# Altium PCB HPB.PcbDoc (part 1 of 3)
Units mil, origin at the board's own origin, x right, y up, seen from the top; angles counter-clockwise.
Board outline 7000 x 12000 mil, 6 copper layers (Top Layer, Int1 (GND), Int2 (Sign), Int3 (Sign), Int4 (PWR), Bottom Layer), stack 61.068 mil thick; 321 components, 232 nets, 1034 pads, 269 vias.
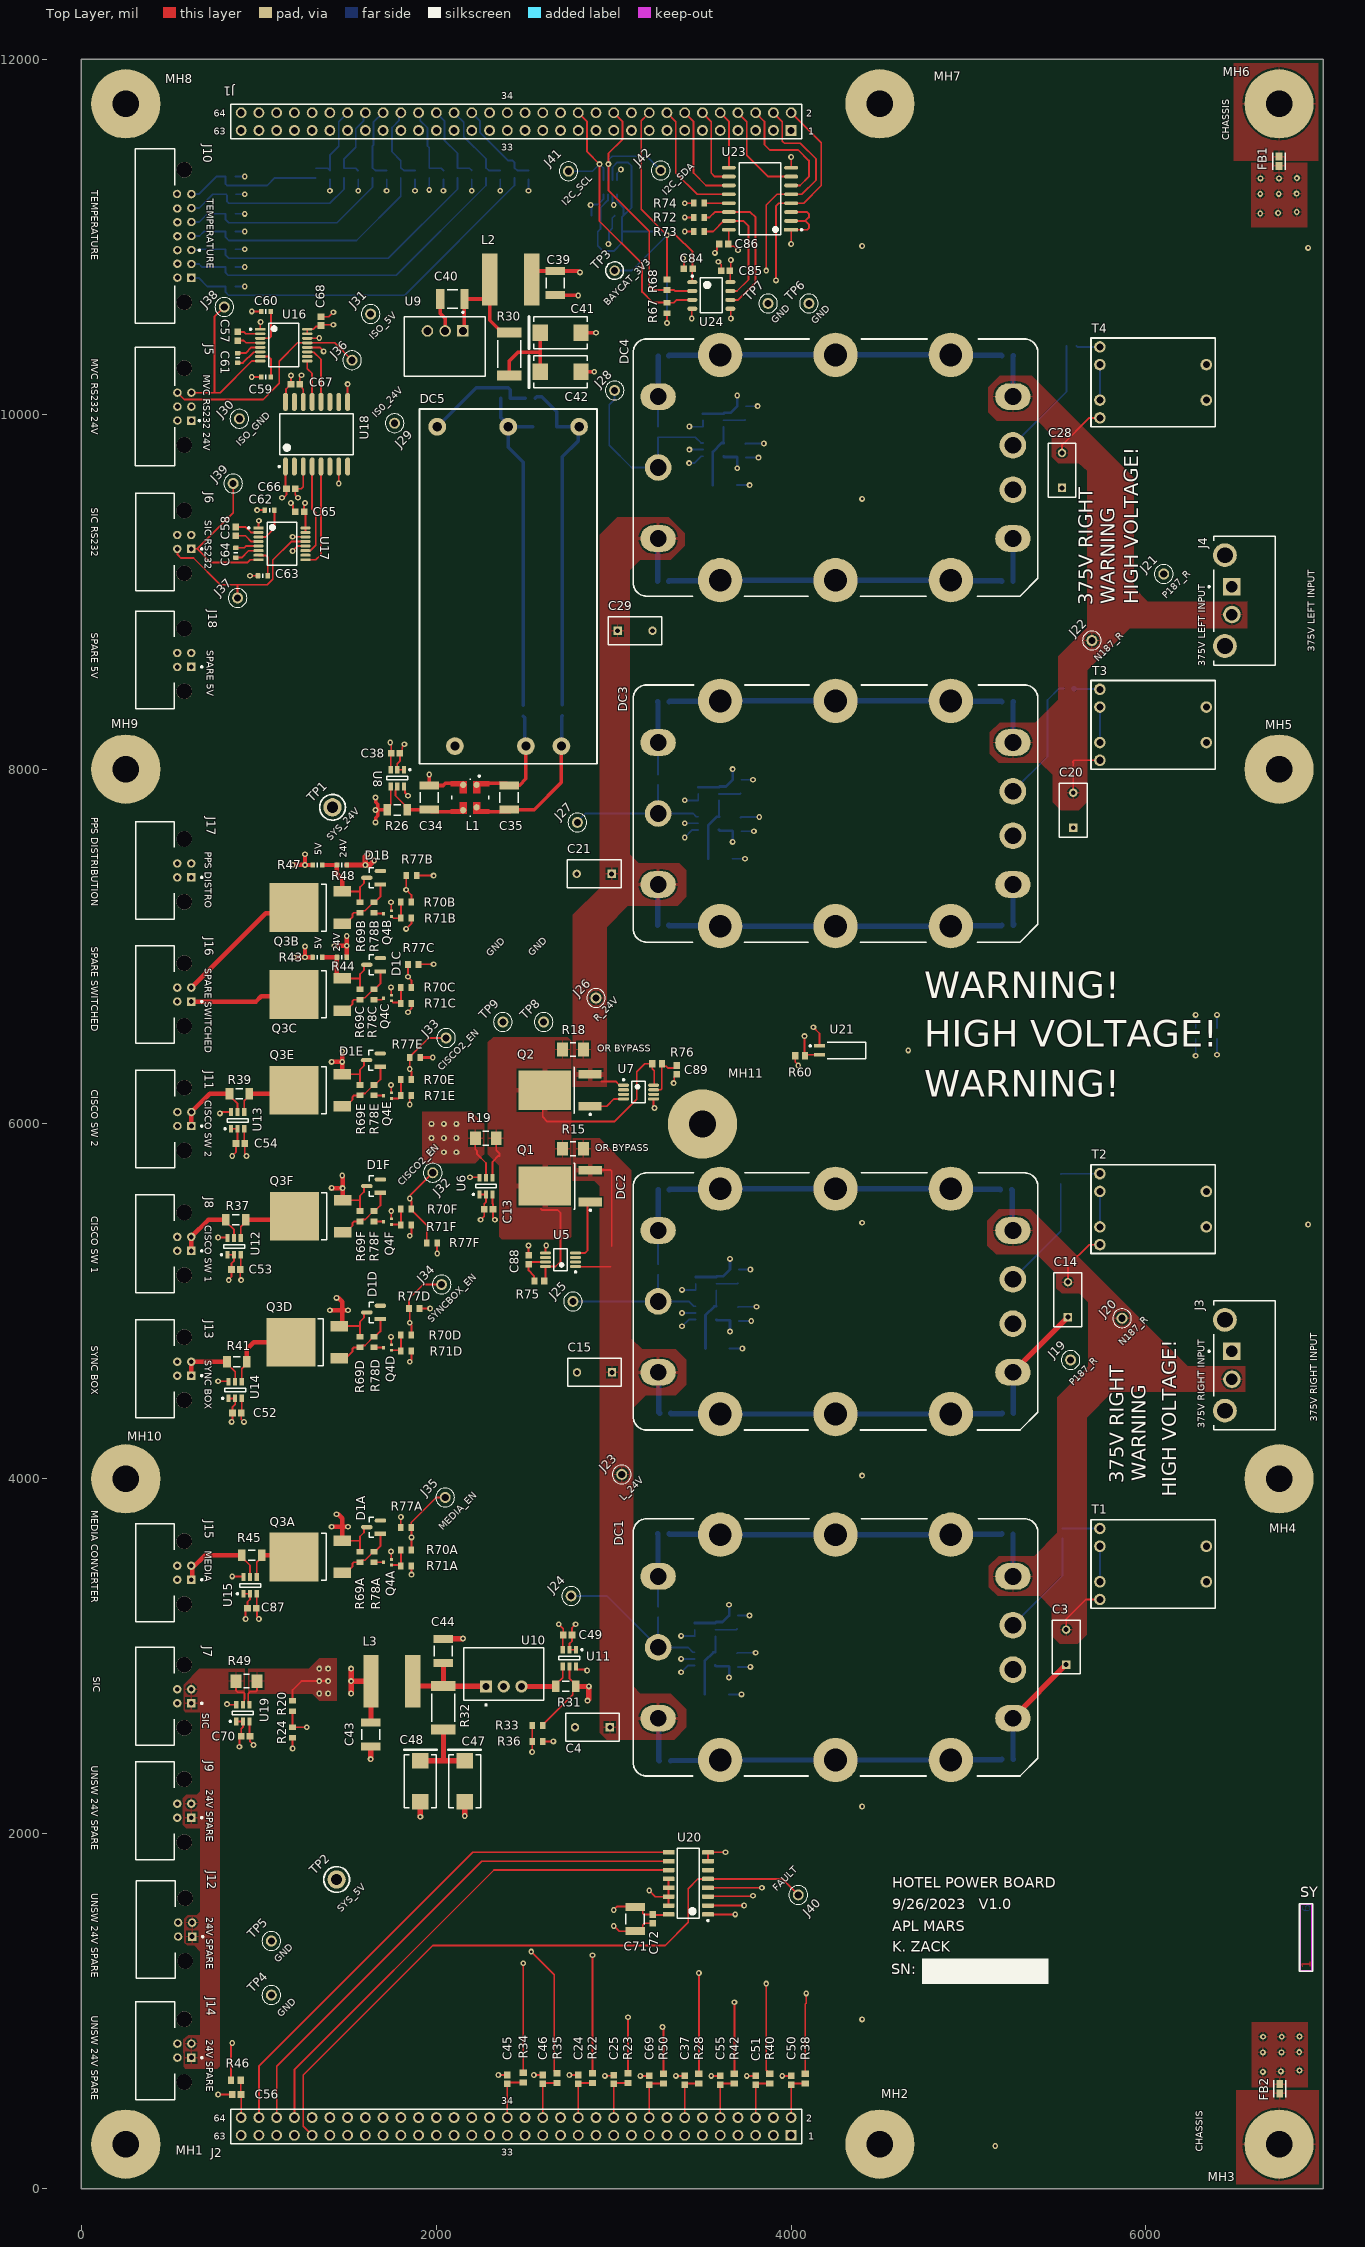
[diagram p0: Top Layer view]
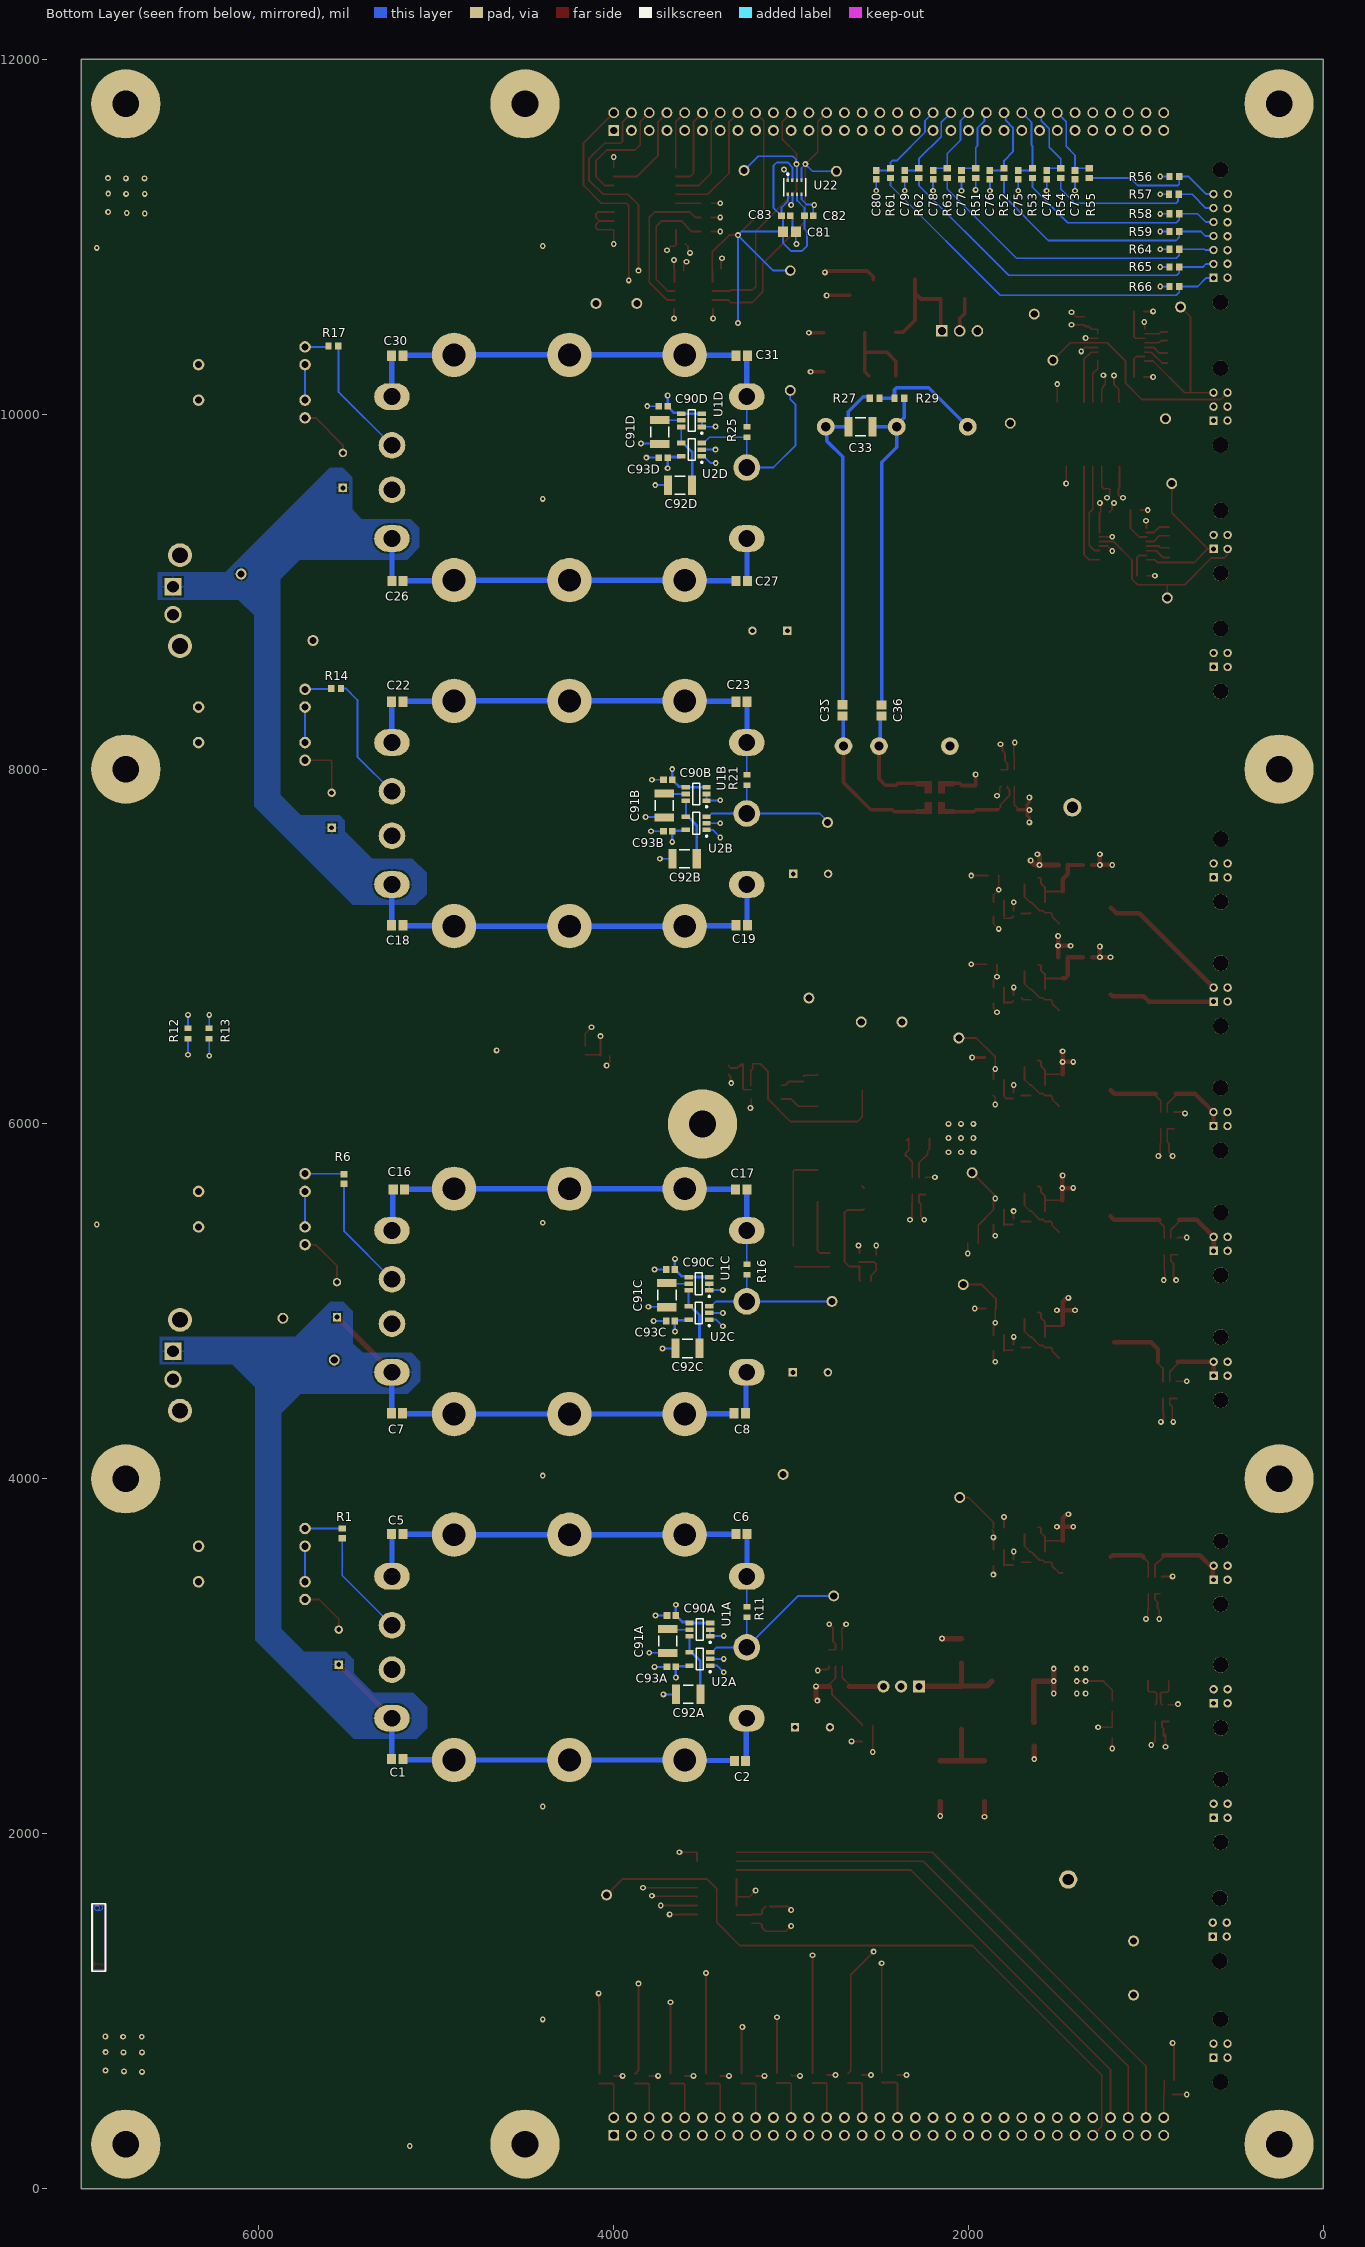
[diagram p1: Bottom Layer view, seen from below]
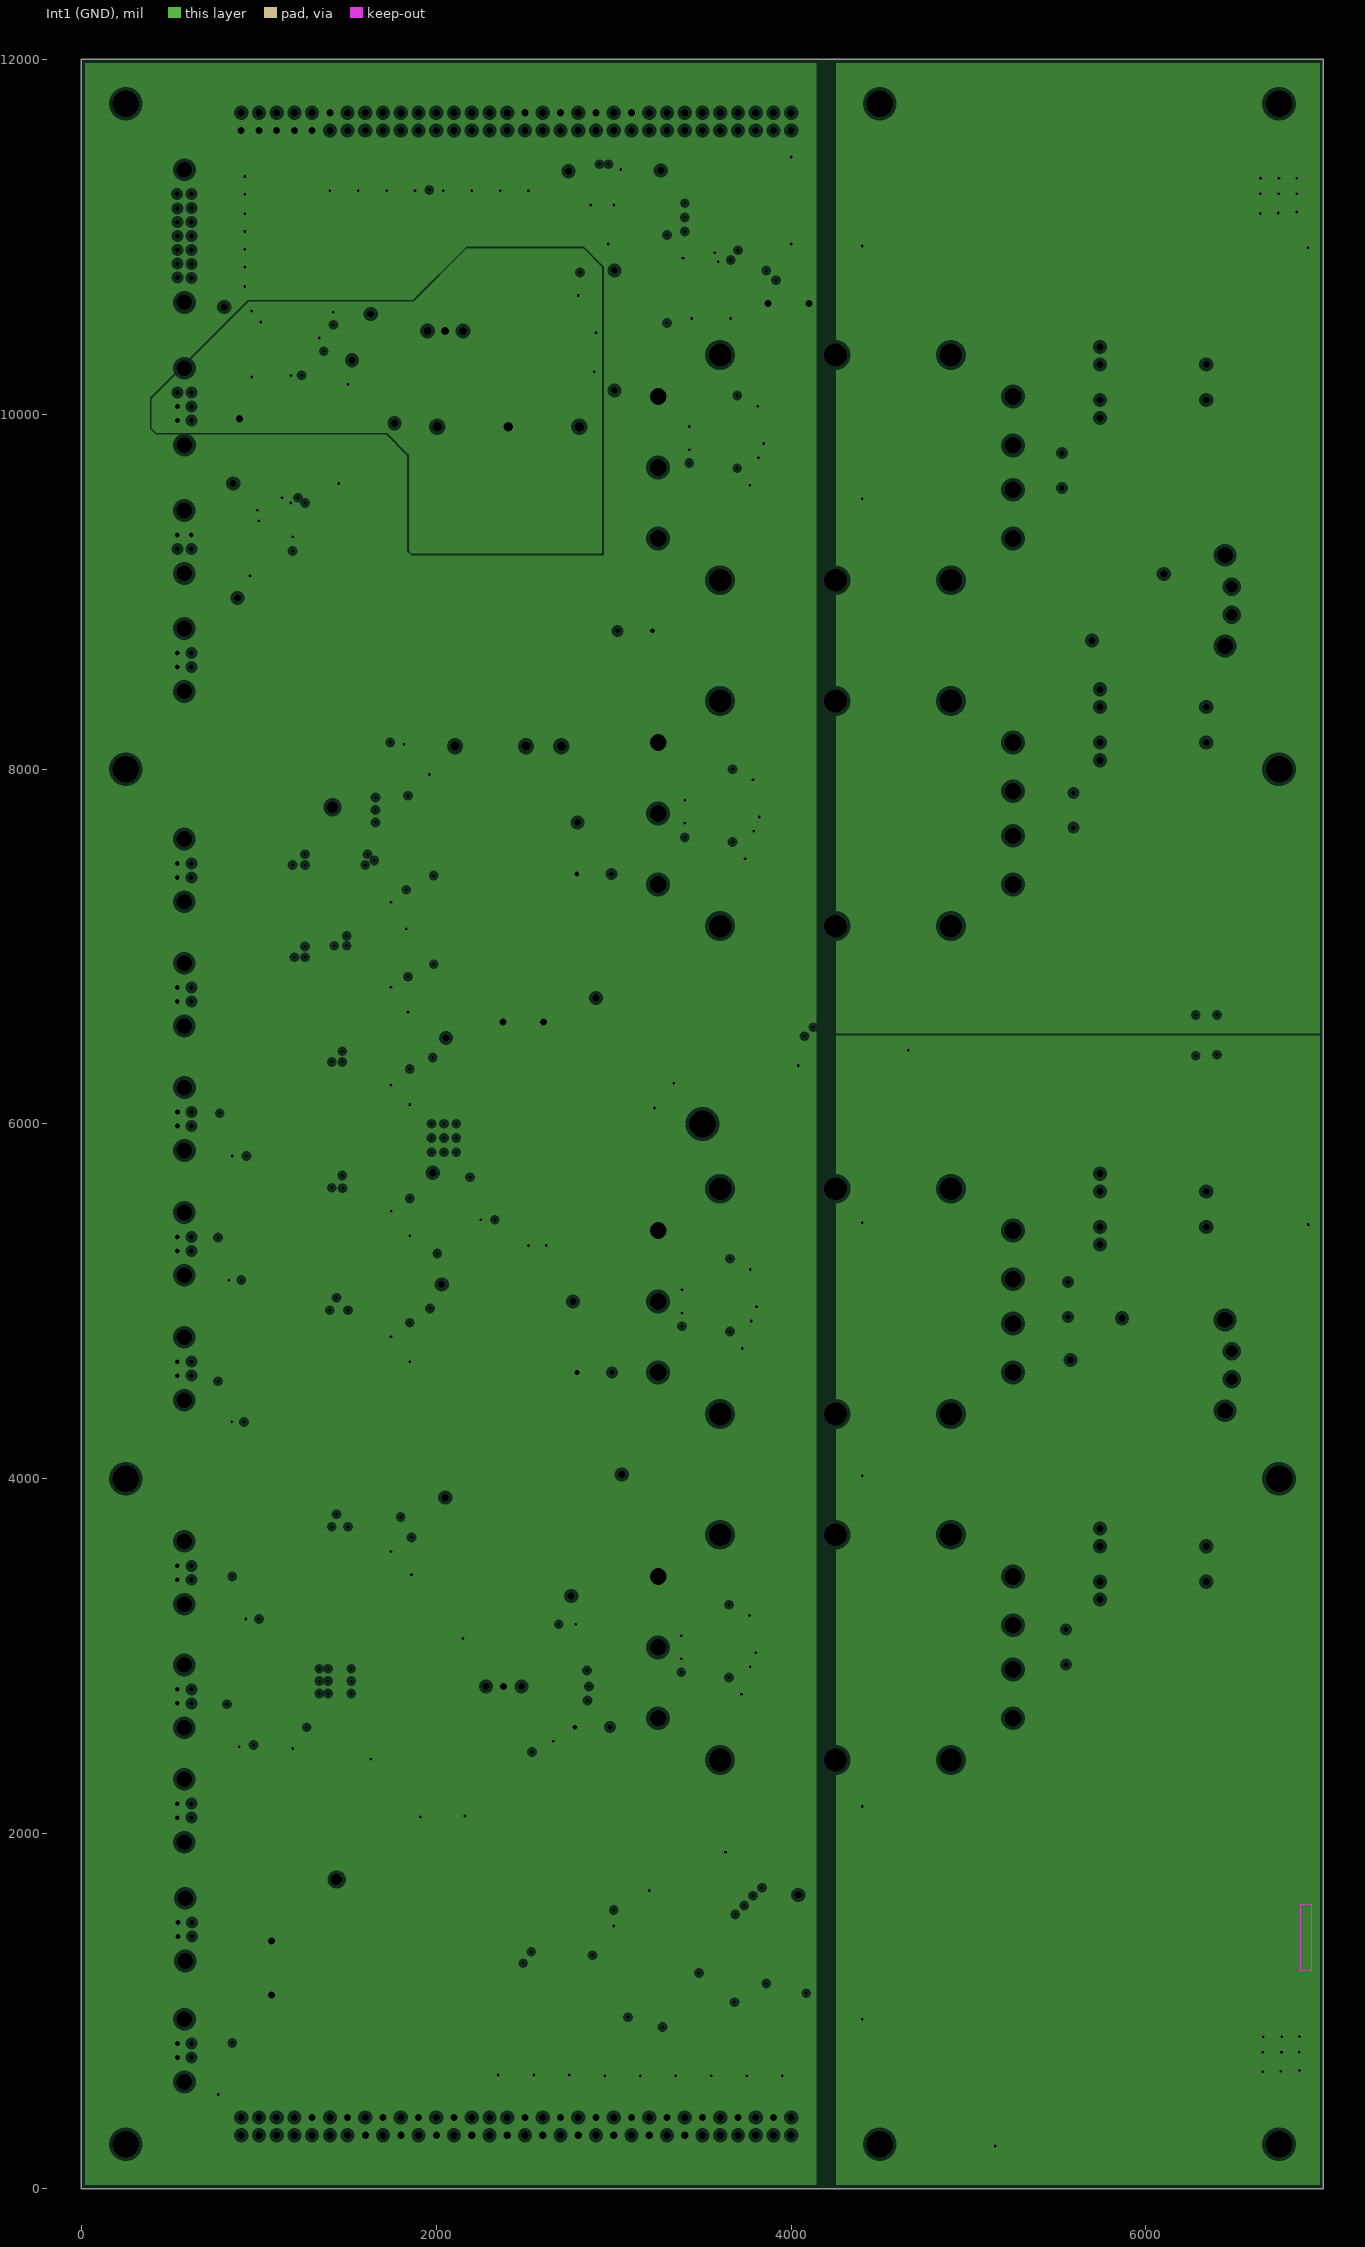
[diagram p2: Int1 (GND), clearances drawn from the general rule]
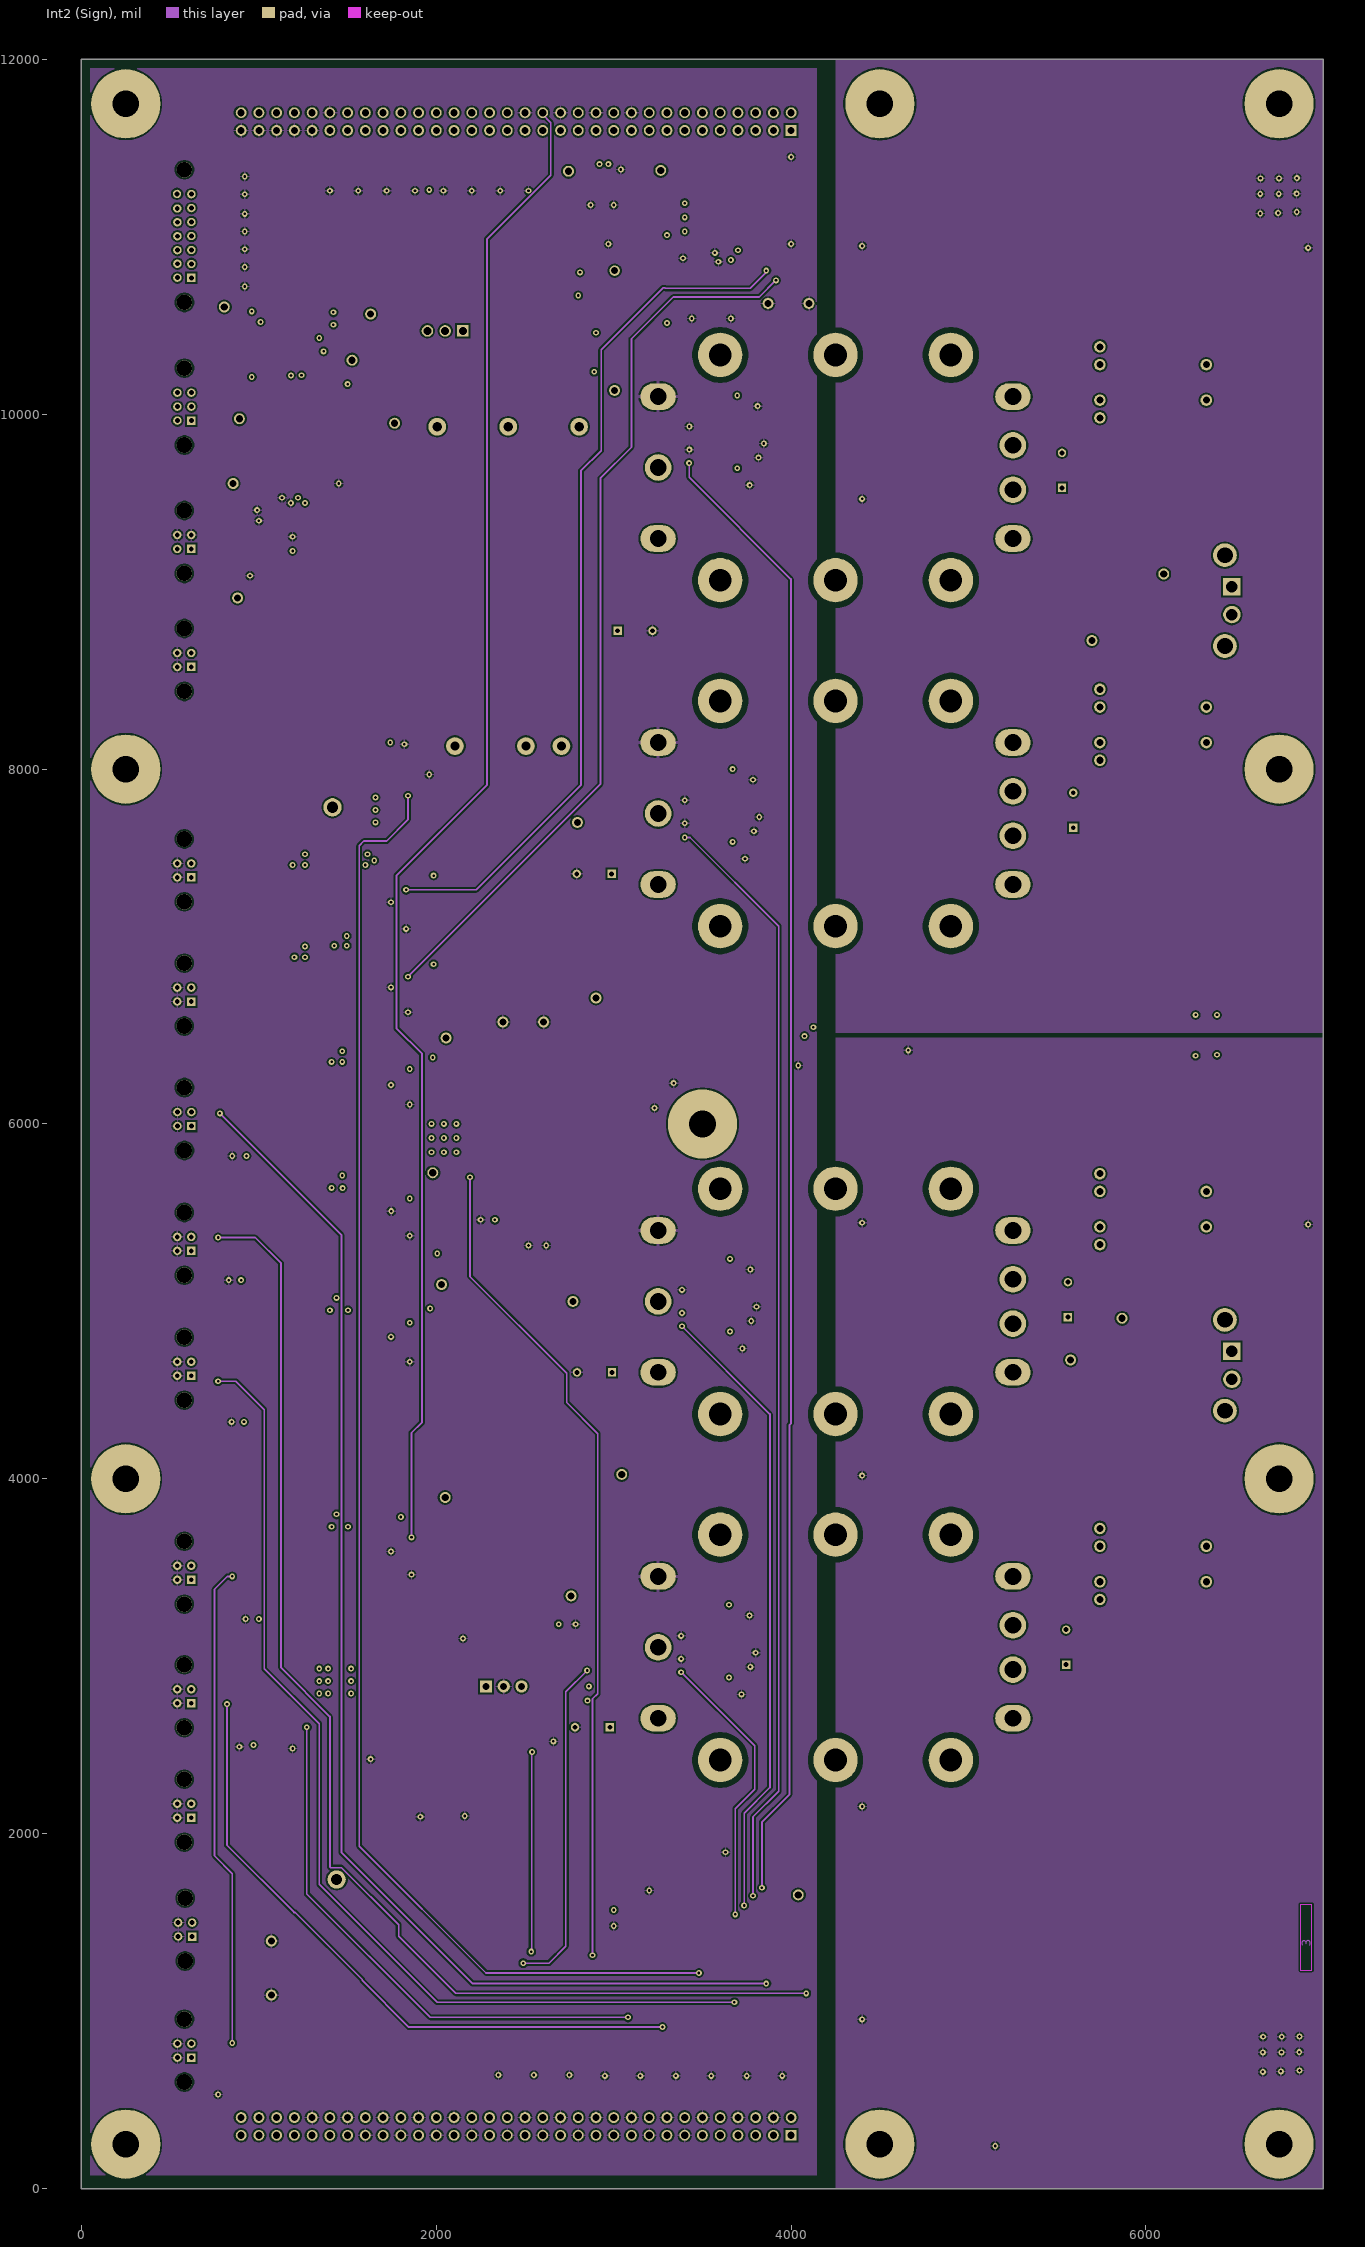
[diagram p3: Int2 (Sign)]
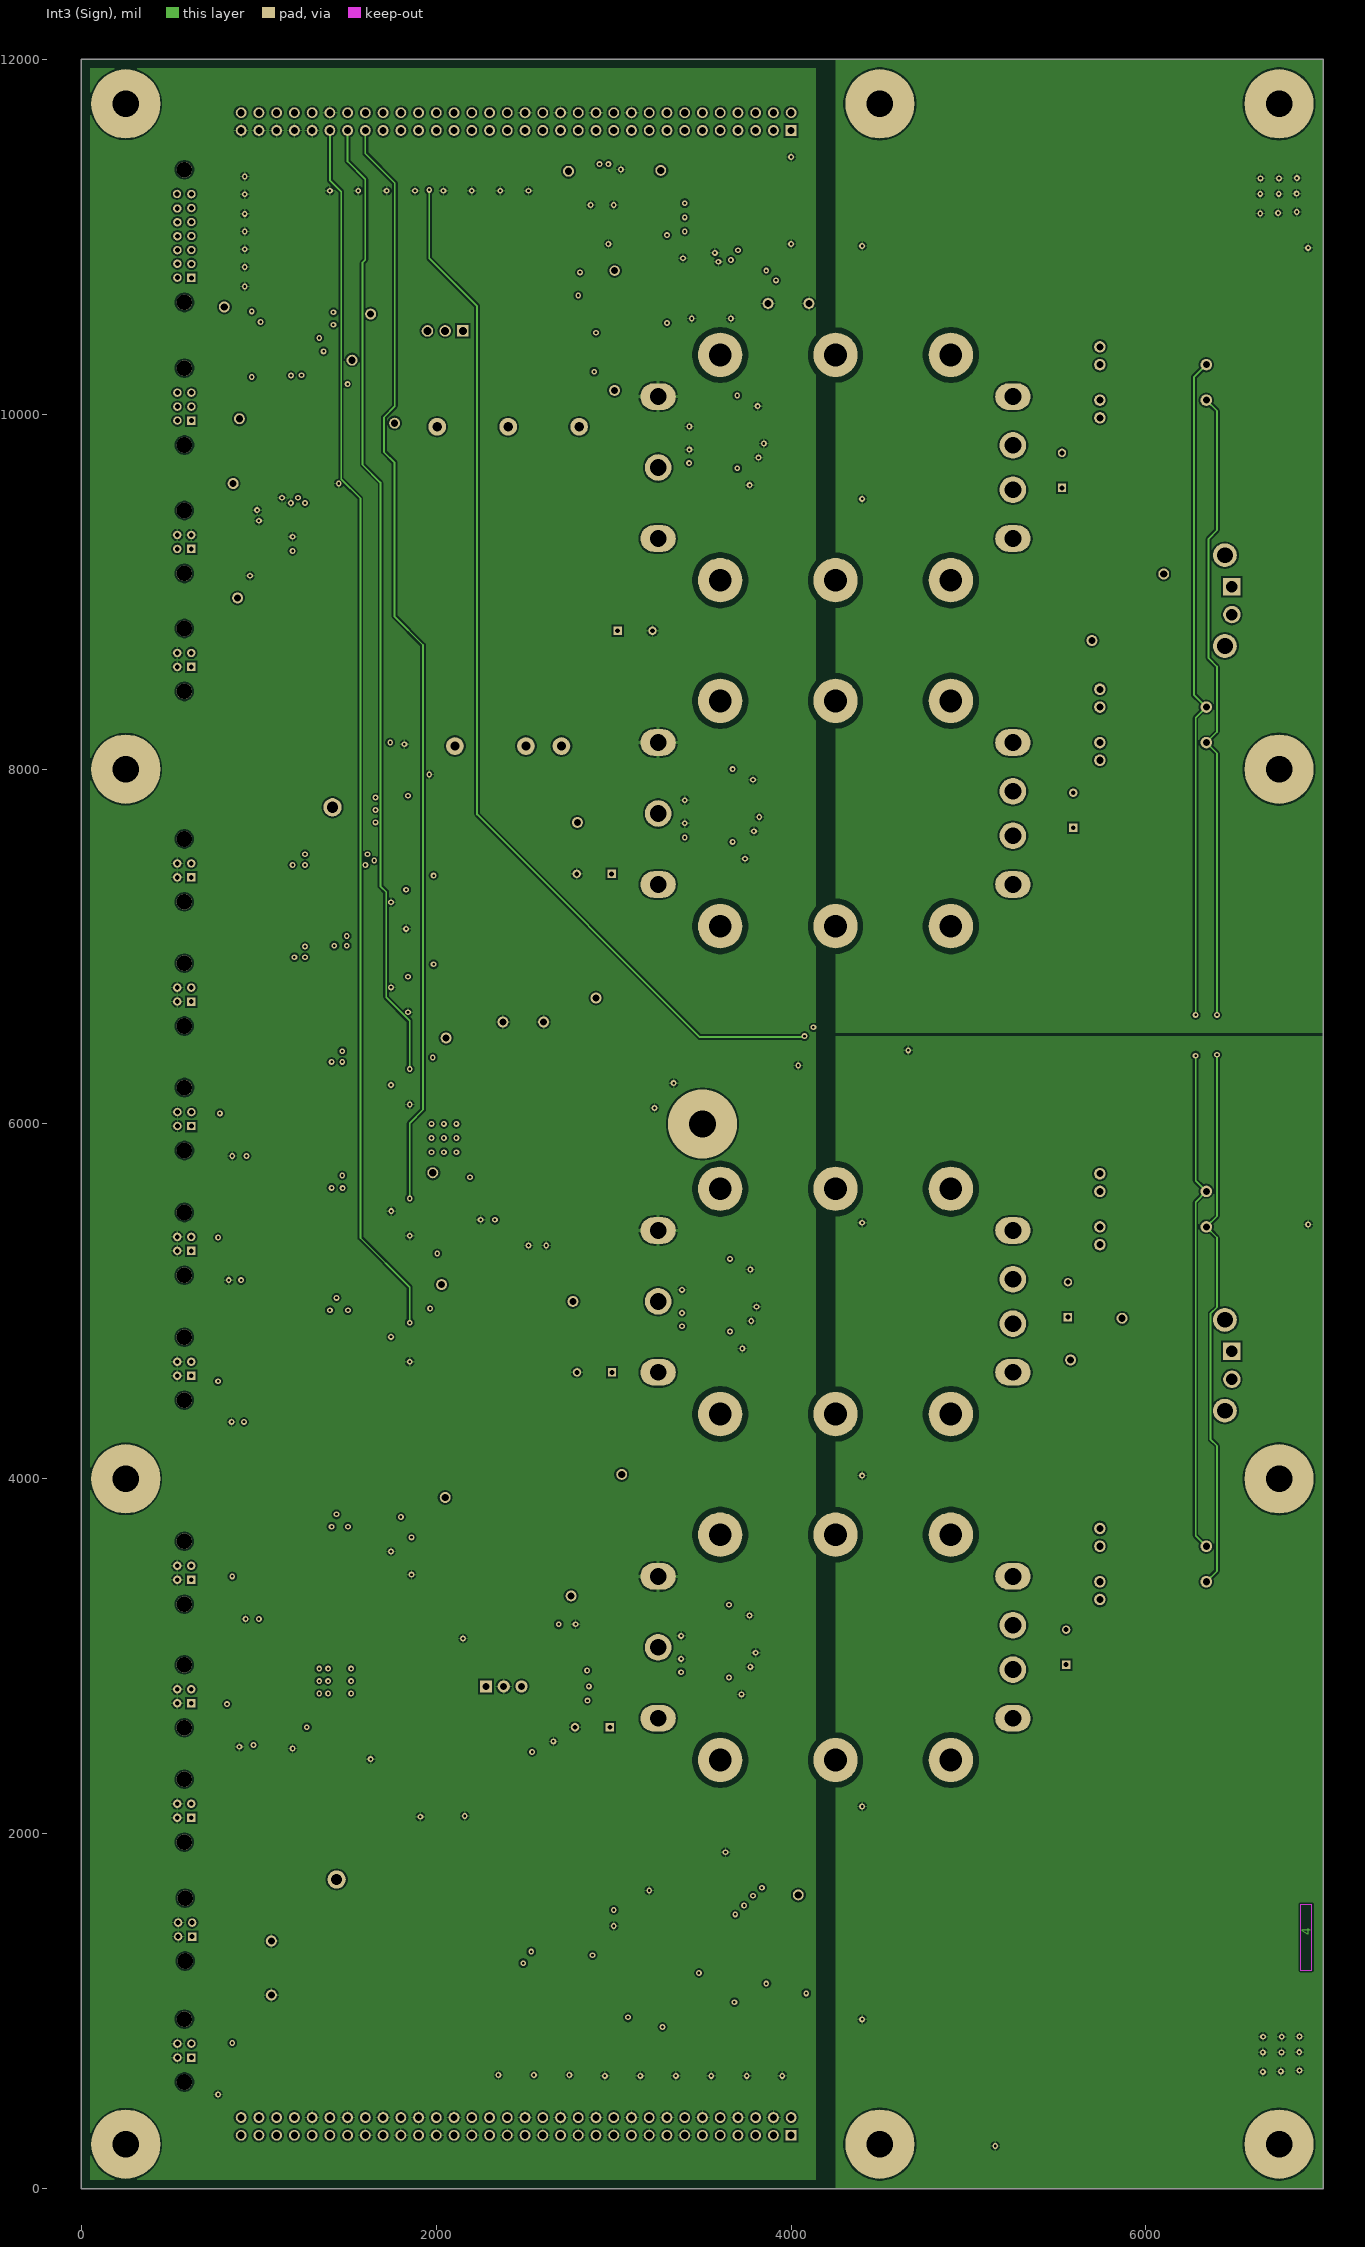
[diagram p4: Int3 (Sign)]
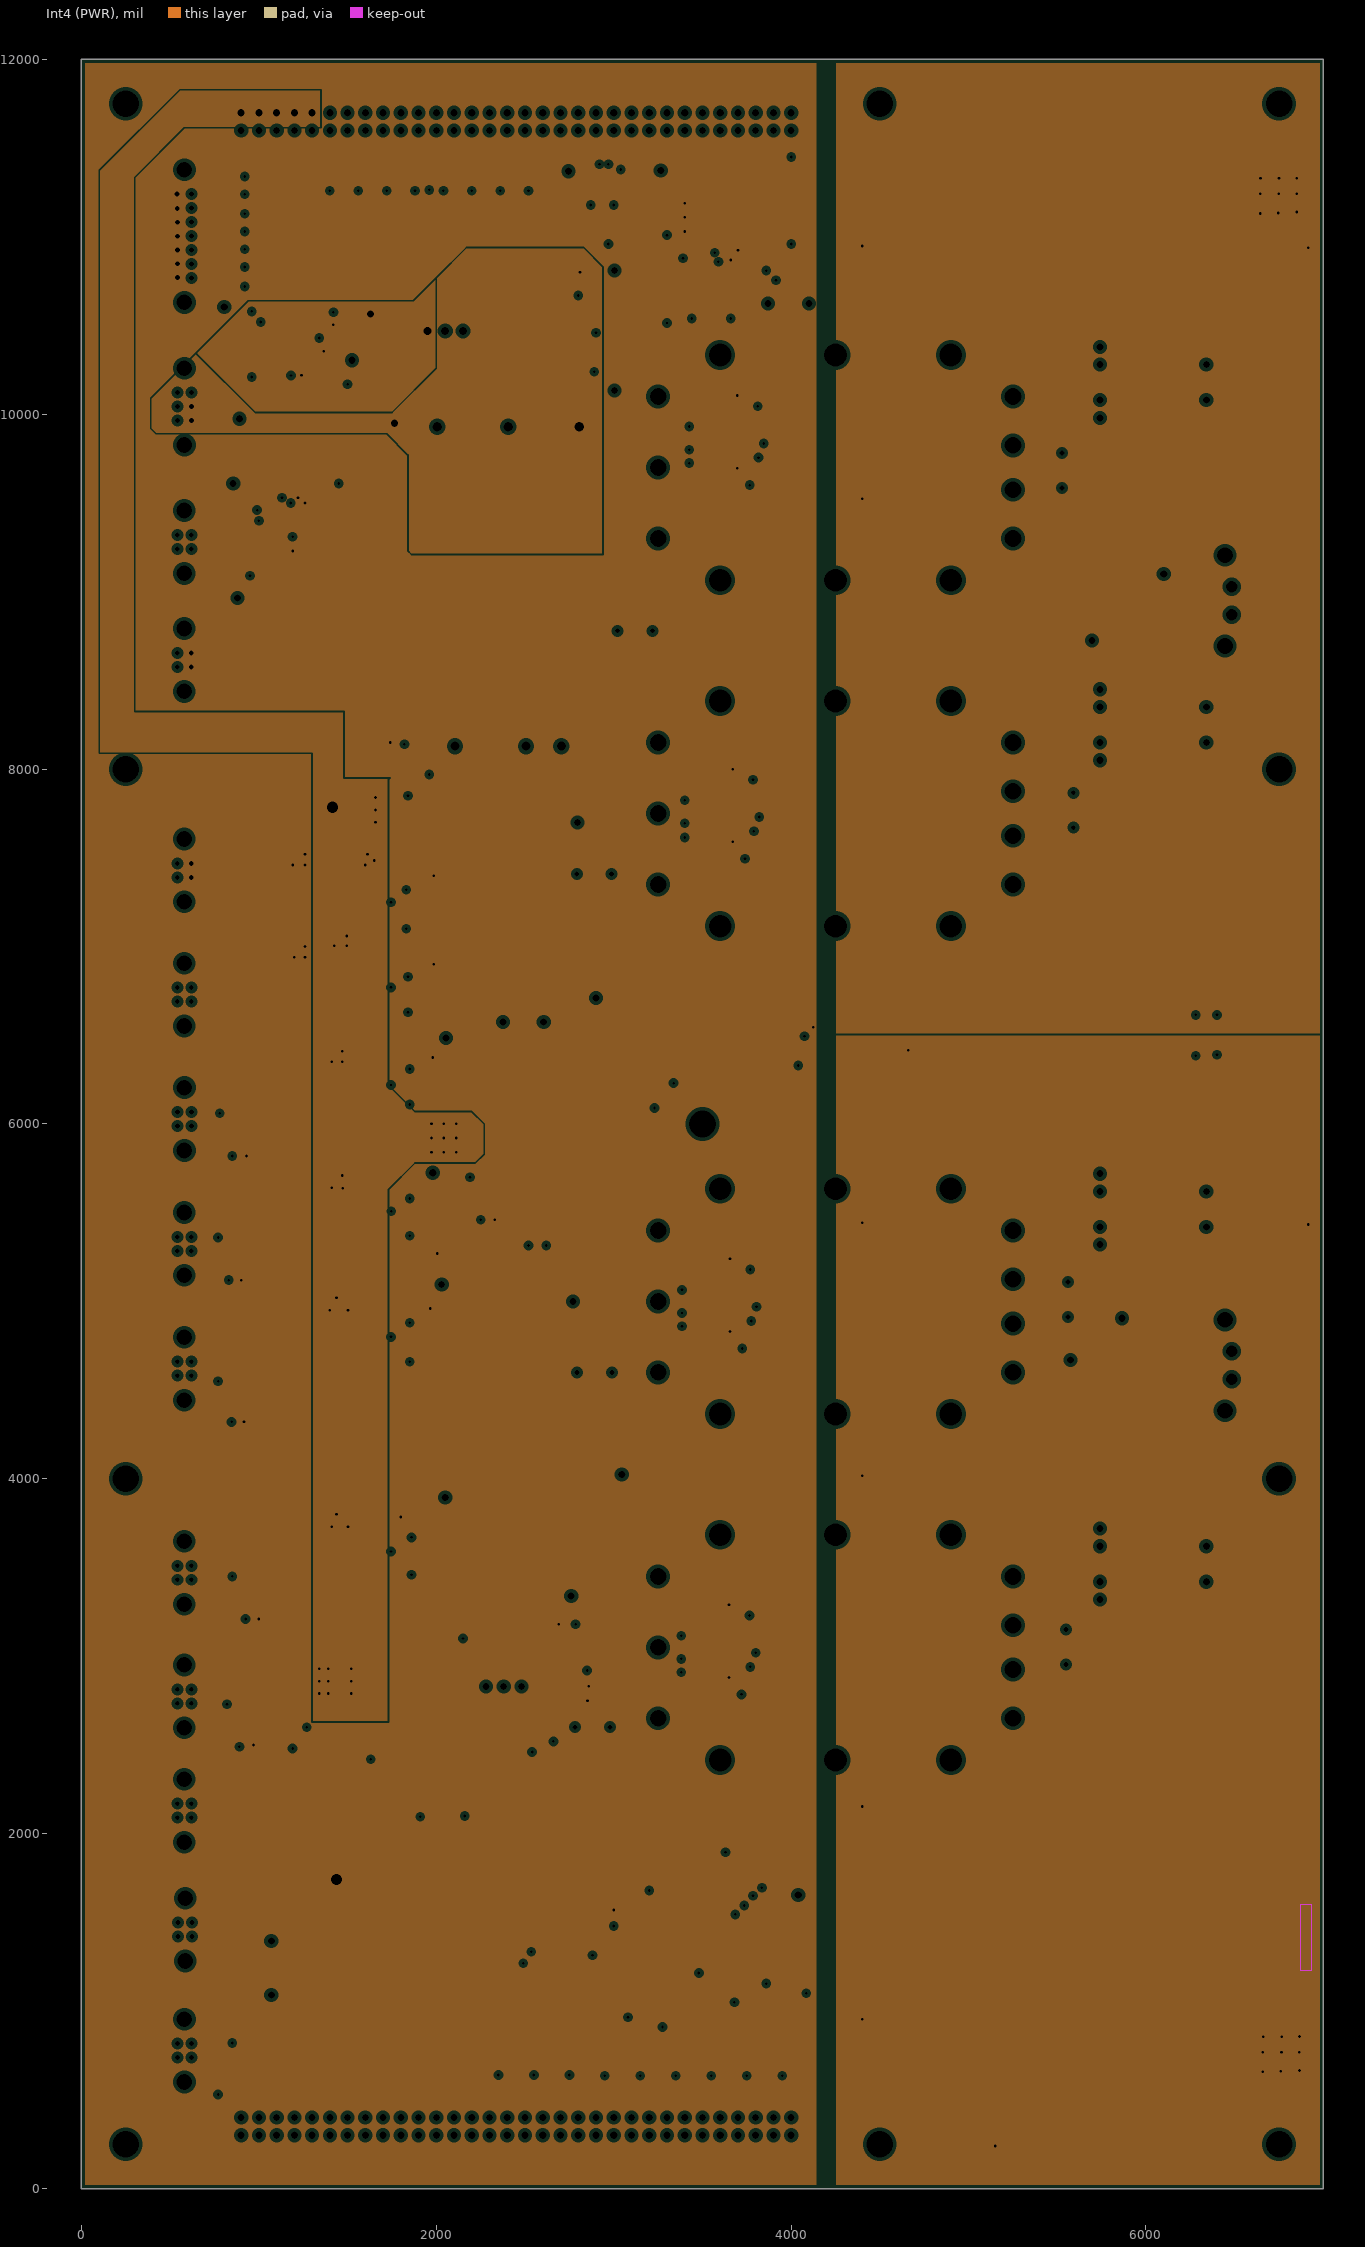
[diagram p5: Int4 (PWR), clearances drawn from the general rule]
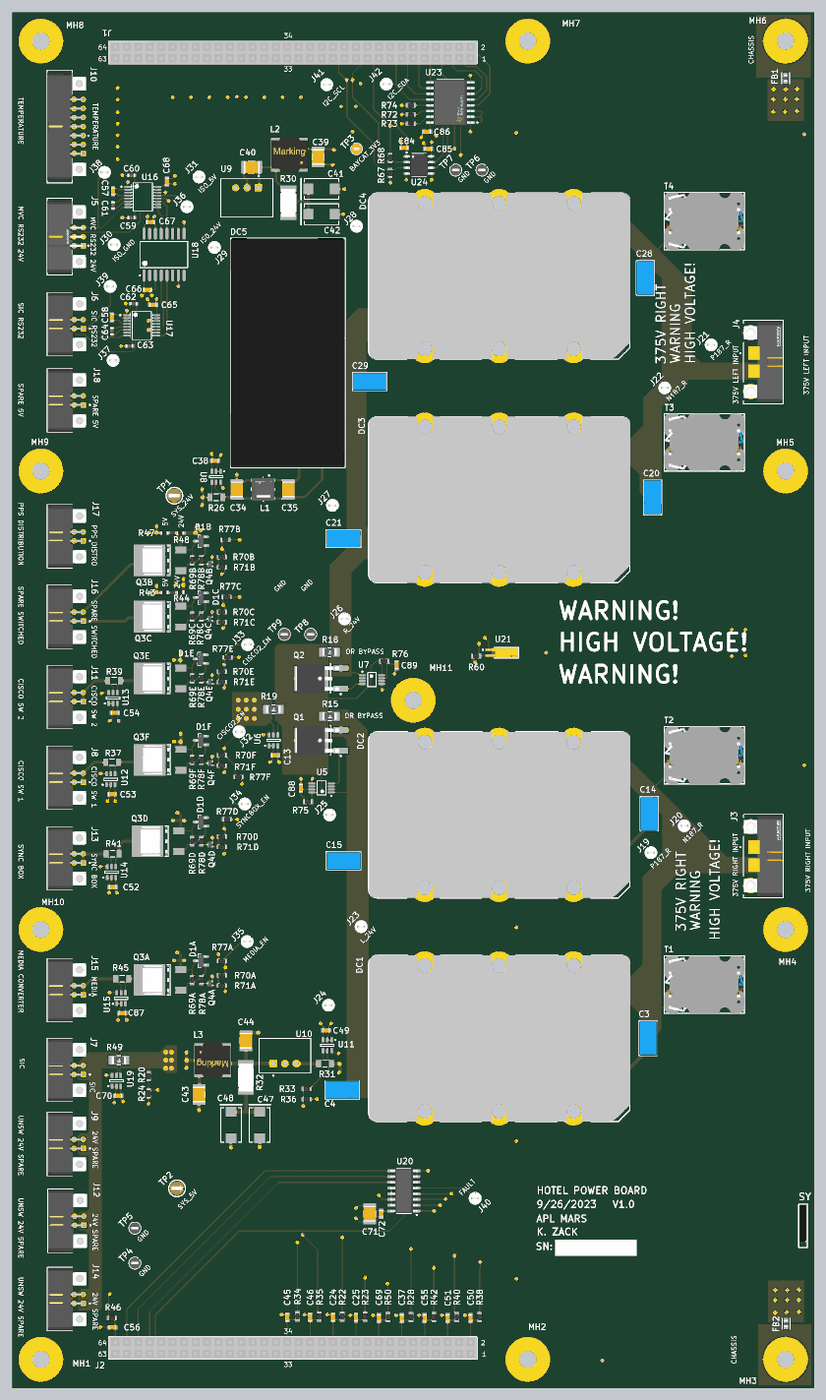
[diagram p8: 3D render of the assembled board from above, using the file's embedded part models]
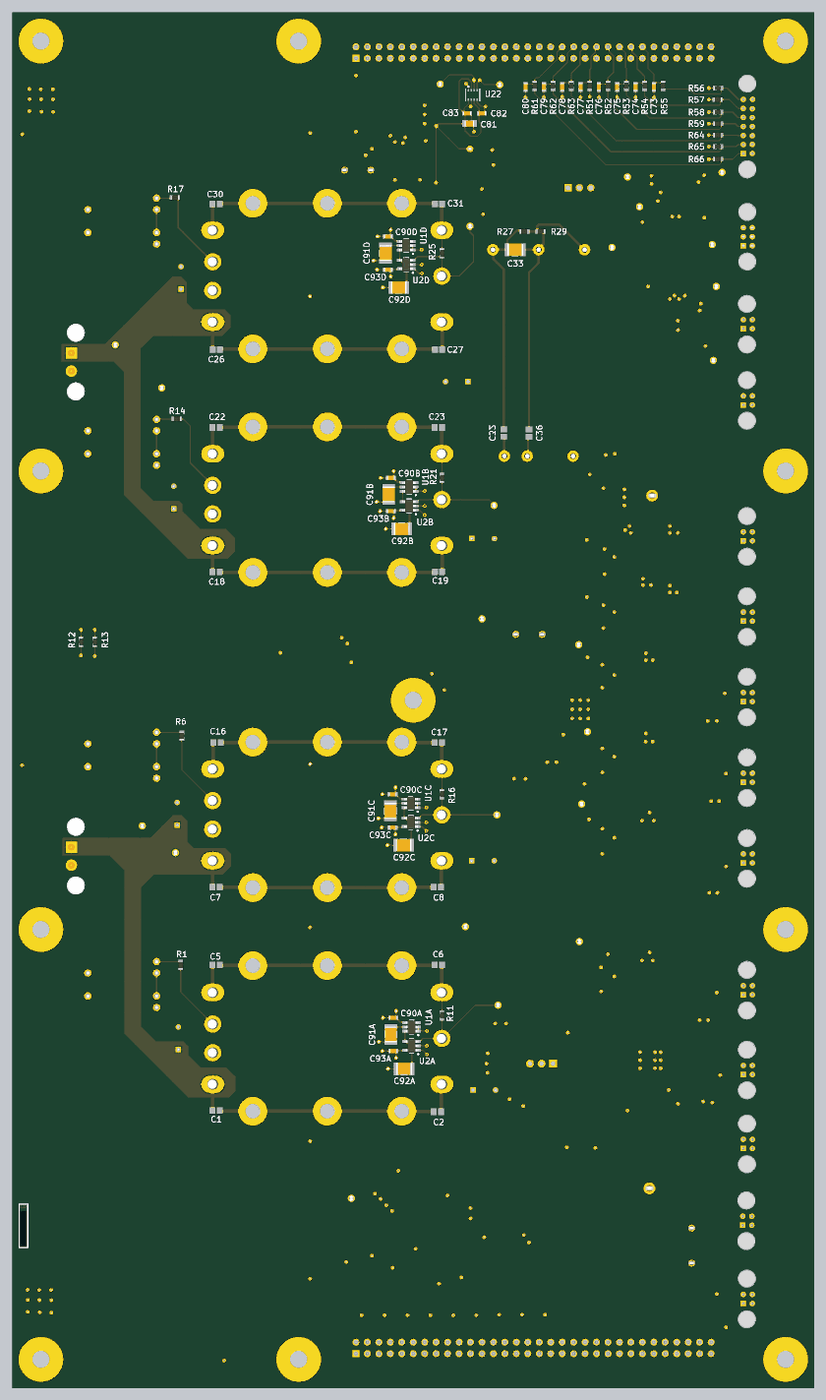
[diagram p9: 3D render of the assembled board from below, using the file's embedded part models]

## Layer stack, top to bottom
Top Solder: solder mask 1, SM-001, Dk 4
Top Layer: signal copper 1.378
Dielectric 1: prepreg 2.8, PP-006, Dk 4.1
Dielectric 2: prepreg 2.8, PP-006, Dk 4.1
Int1 (GND): plane copper 1.378, net (Multiple Nets)
Dielectric 3: core 18, Core-035, Dk 4.7
Int2 (Sign): signal copper 1.378
Dielectric 4: prepreg 2.8, PP-006, Dk 4.1
Dielectric 5: prepreg 2.8, PP-006, Dk 4.1
Int3 (Sign): signal copper 1.378
Dielectric 6: core 18, Core-035, Dk 4.7
Int4 (PWR): plane copper 1.378, net (Multiple Nets)
Dielectric 7: prepreg 2.8, PP-006, Dk 4.1
Dielectric 8: prepreg 2.8, PP-006, Dk 4.1
Bottom Layer: signal copper 1.378
Bottom Solder: solder mask 1, SM-001, Dk 4

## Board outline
0,0 0,12000 7000,12000 7000,0

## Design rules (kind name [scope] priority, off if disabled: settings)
Clearance Clearance_Vicor_MTG [InNetClass('MTG Hole') vs (IsRegion OR IsSplitPlane)] p1: gap=32 ignorepadtopadclearanceinfootprint=TRUE
Clearance [All] p2: gap=10 ignorepadtopadclearanceinfootprint=FALSE except(0: Arc-Hole Track-Hole SMDPad-Hole THPad-Hole Via-Hole Fill-Hole Poly-Hole Region-Hole Text-Hole; 6: Arc-SMDPad Arc-Via Track-SMDPad Track-Via SMDPad-SMDPad)
HoleSize [All] p1: absolutevalues=TRUE maxlimit=700 minlimit=1 maxpercent=80.000 minpercent=20.000
MinimumSolderMaskSliver [All] p1: minsoldermaskwidth=3.8
PlaneClearance [All] p1: clearance=20
PlaneConnect [All] p1: planeconnectstyle=Relief reliefexpansion=20 reliefentries=4 reliefconductorwidth=10 reliefairgap=10
PolygonConnect [All] p1: connectstyle=Relief reliefconductorwidth=10 reliefentries=4 polygonreliefangle="90 Angle" airgapwidth=10
RoutingVias [All] p1: holewidth=15 width=25 viastyle="Through Hole" minholewidth=5 minwidth=10 maxholewidth=30 maxwidth=50
SilkToSilkClearance [All] p1: silktosilkclearance=5
SilkToSolderMaskClearance [IsPad] p1: minsilkscreentomaskgap=5 clearancetoexposedcopper=TRUE
SolderMaskExpansion [All] p1: expansion=4 istentingtop=FALSE
Width [All] p1: maxlimit=100 minlimit=5 preferedwidth=10 minimp=50.000000 maximp=50.000000 favimp=50.000000
24 further rules are at their usual default settings.

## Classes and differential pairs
net class "MTG Hole": V1_L_MT1 V1_L_MT2 V1_R_MT1 V1_R_MT2 V2_L_MT1 V2_L_MT2 V2_R_MT1 V2_R_MT2
channel class 1V024_Comparators: "1.024V Comparator V1-Left" "1.024V Comparator V1-Right" "1.024V Comparator V2-Left" "1.024V Comparator V2-Right"
component class "1.024V Comparator V2-Right": C90D C91D C92D C93D U1D U2D
component class "1.024V Comparator V2-Left": C90C C91C C92C C93C U1C U2C
component class "1.024V Comparator V1-Right": C90B C91B C92B C93B U1B U2B
component class "1.024V Comparator V1-Left": C90A C91A C92A C93A U1A U2A
component class .6: D1F Q3F Q4F R69F R70F R71F R77F R78F
component class .5: D1E Q3E Q4E R69E R70E R71E R77E R78E
component class .4: D1D Q3D Q4D R69D R70D R71D R77D R78D
component class I2C_GPIO: C84 C85 C86 R72 R73 R74 U23 U24
component class Temperature: C73 C74 C75 C76 C77 C78 C79 C80 C81 C82 C83 J41 J42 R51 R52 R53 R54 R55 R56 R57 R58 R59 R60 R61 R62 R63 R64 R65 R66 R67 R68 TP3 U21 U22
component class Switches: C50 C51 C52 C53 C54 C55 C56 C87 J32 J33 J34 J35 R37 R38 R39 R40 R41 R42 R43 R44 R45 R46 R47 R48 U12 U13 U14 U15
component class "RS232 Isolator": C57 C58 C59 C60 C61 C62 C63 C64 C65 C66 C67 C68 J36 J37 J38 J39 U16 U17 U18
component class "Fault Mux": C71 C72 J40 U20
component class Coversheet: FB1 FB2 MH1 MH2 MH3 MH4 MH5 MH6 MH7 MH8 MH9 MH10 MH11 SY
channel class P-CH_SWITCH: .1 .2 .3 .4 .5 .6
component class .3: D1C Q3C Q4C R69C R70C R71C R77C R78C
component class .2: D1B Q3B Q4B R69B R70B R71B R77B R78B
component class .1: D1A Q3A Q4A R69A R70A R71A R77A R78A
component class "Output Connectors": C69 C70 J6 J7 J8 J9 J10 J11 J12 J13 J14 J15 J16 J17 J18 R49 R50 U19
component class "MVC Connector": J5
component class "Mezzanine Connector": J1 J2
component class "IGB Power Connector": J3 J4 J19 J20 J21 J22
component class "24V ISO": C32 C33 C34 C35 C36 C37 C38 C39 C40 C41 C42 DC5 J29 J30 J31 L1 L2 R26 R27 R28 R29 R30 U8 U9
component class "24V Bus Power Supply": C1 C2 C3 C4 C5 C6 C7 C8 C13 C14 C15 C16 C17 C18 C19 C20 C21 C22 C23 C24 C25 C26 C27 C28 C29 C30 C31 C88 C89 DC1 DC2 DC3 DC4 J23 J24 J25 J26 J27 J28 Q1 Q2 R1 R6 R11 R12 R13 R14 R15 R16 R17 R18 R19 R20 R21 R22 R23 R24 R25 R75 R76 T1 T2 T3 T4 TP1 U5 U6 U7
component class "5V Power Supply": C43 C44 C45 C46 C47 C48 C49 L3 R31 R32 R33 R34 R35 R36 TP2 TP4 TP5 TP6 TP7 TP8 TP9 U10 U11

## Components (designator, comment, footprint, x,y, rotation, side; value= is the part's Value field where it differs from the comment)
C1 "Capacitor 4.7nF 10%, 1kV, X7R, 0805" CAPC2013X145X50NL20T25 5220,2420 r180 bottom value=4.7nF
C2 "Capacitor 4.7nF 10%, 1kV, X7R, 0805" CAPC2013X145X50NL20T25 3288.5,2410 r180 bottom value=4.7nF
C3 "Capacitor 0.22uF, 20%, 1kV,X7R,Radial" FP-RDEUE1+0_5-MFG 5550,3051.57 r90 top value=220nF
C4 "Capacitor 0.22uF, 20%, 1kV,X7R,Radial" FP-RDEUE1+0_5-MFG 2880,2600 r180 top value=220nF
C5 "Capacitor 4.7nF 10%, 1kV, X7R, 0805" CAPC2013X145X50NL20T25 5220,3690 r180 bottom value=4.7nF
C6 "Capacitor 4.7nF 10%, 1kV, X7R, 0805" CAPC2013X145X50NL20T25 3280,3690 r180 bottom value=4.7nF
C7 "Capacitor 4.7nF 10%, 1kV, X7R, 0805" CAPC2013X145X50NL20T25 5221.5,4370 r180 bottom value=4.7nF
C8 "Capacitor 4.7nF 10%, 1kV, X7R, 0805" CAPC2013X145X50NL20T25 3290,4370 r180 bottom value=4.7nF
C13 "Capacitor 100 nF +/-10% 50 V 0603" CAPC1608X90X40NL10T20 2294.61,5520 r0 top value=100nF
C14 "Capacitor 0.22uF, 20%, 1kV,X7R,Radial" FP-RDEUE1+0_5-MFG 5560,5010 r90 top value=220nF
C15 "Capacitor 0.22uF, 20%, 1kV,X7R,Radial" FP-RDEUE1+0_5-MFG 2891.57,4600 r180 top value=220nF
C16 "Capacitor 4.7nF 10%, 1kV, X7R, 0805" CAPC2013X145X50NL20T25 5211.5,5630 r180 bottom value=4.7nF
C17 "Capacitor 4.7nF 10%, 1kV, X7R, 0805" CAPC2013X145X50NL20T25 3281.5,5630 r180 bottom value=4.7nF
C18 "Capacitor 4.7nF 10%, 1kV, X7R, 0805" CAPC2013X145X50NL20T25 5220,7120 r180 bottom value=4.7nF
C19 "Capacitor 4.7nF 10%, 1kV, X7R, 0805" CAPC2013X145X50NL20T25 3278.5,7120 r180 bottom value=4.7nF
C20 "Capacitor 0.22uF, 20%, 1kV,X7R,Radial" FP-RDEUE1+0_5-MFG 5590,7768.43 r90 top value=220nF
C21 "Capacitor 0.22uF, 20%, 1kV,X7R,Radial" FP-RDEUE1+0_5-MFG 2890,7410 r180 top value=220nF
C22 "Capacitor 4.7nF 10%, 1kV, X7R, 0805" CAPC2013X145X50NL20T25 5220,8380 r180 bottom value=4.7nF
C23 "Capacitor 4.7nF 10%, 1kV, X7R, 0805" CAPC2013X145X50NL20T25 3280,8380 r180 bottom value=4.7nF
C24 "Capacitor 100 nF +/-10% 50 V 0603" CAPC1608X90X40NL10T20 2800,615.39 r270 top value=100nF
C25 "Capacitor 100 nF +/-10% 50 V 0603" CAPC1608X90X40NL10T20 3000,614.61 r270 top value=100nF
C26 "Capacitor 4.7nF 10%, 1kV, X7R, 0805" CAPC2013X145X50NL20T25 5218.5,9060 r180 bottom value=4.7nF
C27 "Capacitor 4.7nF 10%, 1kV, X7R, 0805" CAPC2013X145X50NL20T25 3278.5,9060 r180 bottom value=4.7nF
C28 "Capacitor 0.22uF, 20%, 1kV,X7R,Radial" FP-RDEUE1+0_5-MFG 5526.59,9684.18 r90 top value=220nF
C29 "Capacitor 0.22uF, 20%, 1kV,X7R,Radial" FP-RDEUE1+0_5-MFG 3120,8780 r0 top value=220nF
C30 "Capacitor 4.7nF 10%, 1kV, X7R, 0805" CAPC2013X145X50NL20T25 5220,10330 r180 bottom value=4.7nF
C31 "Capacitor 4.7nF 10%, 1kV, X7R, 0805" CAPC2013X145X50NL20T25 3278.5,10330 r180 bottom value=4.7nF
C32 "Capacitor 4.7nF 10%, 1kV, X7R, 0805" CAPC2013X145X50NL20T25 2710,8331.5 r90 bottom value=4.7nF
C33 "Capacitor 10uF 10%, 50V, X7R, 1210" CAPC3225X270X30ML30 2610,9930 r0 bottom value=10uF
C34 "Capacitor 10uF 10%, 50V, X7R, 1210" CAPC3225X270X30ML30 1960,7840 r270 top value=10uF
C35 "Capacitor 10uF 10%, 50V, X7R, 1210" CAPC3225X270X30ML30 2410,7840 r270 top value=10uF
C36 "Capacitor 4.7nF 10%, 1kV, X7R, 0805" CAPC2013X145X50NL20T25 2490,8330 r90 bottom value=4.7nF
C37 "Capacitor 100 nF +/-10% 50 V 0603" CAPC1608X90X40NL10T20 3400,610 r270 top value=100nF
C38 "Capacitor 100 nF +/-10% 50 V 0603" CAPC1608X90X40NL10T20 1770,8090 r180 top value=100nF
C39 "Capacitor 10uF 10%, 50V, X7R, 1210" CAPC3225X270X30ML30 2670,10740 r90 top value=10uF
C40 "Capacitor 4.7uF 10%, 50V, X7R, 1210" CAPC3225X270X30ML30 2090,10650 r0 top value=4.7uF
C41 "T491D106K050AT" KEMT-D-7343-31-2_L 2700,10460 r0 top value=10uF
C42 "T491D106K050AT" KEMT-D-7343-31-2_L 2700,10240 r0 top value=10uF
C43 "Capacitor 10uF 10%, 50V, X7R, 1210" CAPC3225X270X30ML30 1630,2560 r90 top value=10uF
C44 "Capacitor 4.7uF 10%, 50V, X7R, 1210" CAPC3225X270X30ML30 2040,3030 r270 top value=4.7uF
C45 "Capacitor 100 nF +/-10% 50 V 0603" CAPC1608X90X40NL10T20 2400,615 r270 top value=100nF
C46 "Capacitor 100 nF +/-10% 50 V 0603" CAPC1608X90X40NL10T20 2600,615 r270 top value=100nF
C47 "T491D106K050AT" KEMT-D-7343-31-2_L 2160,2295 r270 top value=10uF
C48 "T491D106K050AT" KEMT-D-7343-31-2_L 1910,2295 r270 top value=10uF
C49 "Capacitor 100 nF +/-10% 50 V 0603" CAPC1608X90X40NL10T20 2740,3120 r180 top value=100nF
C50 "Capacitor 100 nF +/-10% 50 V 0603" CAPC1608X90X40NL10T20 4000,610 r270 top value=100nF
C51 "Capacitor 100 nF +/-10% 50 V 0603" CAPC1608X90X40NL10T20 3800,610 r270 top value=100nF
C52 "Capacitor 100 nF +/-10% 50 V 0603" CAPC1608X90X40NL10T20 876.1,4370.83 r0 top value=100nF
C53 "Capacitor 100 nF +/-10% 50 V 0603" CAPC1608X90X40NL10T20 870,5180 r0 top value=100nF
C54 "Capacitor 100 nF +/-10% 50 V 0603" CAPC1608X90X40NL10T20 895.39,5890 r0 top value=100nF
C55 "Capacitor 100 nF +/-10% 50 V 0603" CAPC1608X90X40NL10T20 3600,610 r270 top value=100nF
C56 "Capacitor 100 nF +/-10% 50 V 0603" CAPC1608X90X40NL10T20 874.61,530 r0 top value=100nF
C57 "Capacitor 100 nF +/-10% 50 V 0603" CAPC1608X90X40NL10T20 880,10440 r270 top value=100nF
C58 "Capacitor 100 nF +/-10% 50 V 0603" CAPC1608X90X40NL10T20 870,9340 r90 top value=100nF
C59 "Capacitor 470nF +/-20% 25V 0603" CAPC0603(1608)100_L 1040,10210 r0 top value=470nF
C60 "Capacitor 470nF +/-20% 25V 0603" CAPC0603(1608)100_L 1040,10580 r0 top value=470nF
C61 "Capacitor 470nF +/-20% 25V 0603" CAPC0603(1608)100_L 880,10317.56 r90 top value=470nF
C62 "Capacitor 470nF +/-20% 25V 0603" CAPC0603(1608)100_L 1060,9460 r0 top value=470nF
C63 "Capacitor 470nF +/-20% 25V 0603" CAPC0603(1608)100_L 1022.44,9090 r0 top value=470nF
C64 "Capacitor 470nF +/-20% 25V 0603" CAPC0603(1608)100_L 870,9220 r270 top value=470nF
C65 "Capacitor 100 nF +/-10% 50 V 0603" CAPC1608X90X40NL10T20 1230,9450 r0 top value=100nF
C66 "Capacitor 100 nF +/-10% 50 V 0603" CAPC1608X90X40NL10T20 1180,9580 r0 top value=100nF
C67 "Capacitor 100 nF +/-10% 50 V 0603" CAPC1608X90X40NL10T20 1205.39,10170 r0 top value=100nF
C68 "Capacitor 100 nF +/-10% 50 V 0603" CAPC1608X90X40NL10T20 1350,10525 r270 top value=100nF
C69 "Capacitor 100 nF +/-10% 50 V 0603" CAPC1608X90X40NL10T20 3200,610 r270 top value=100nF
C70 "Capacitor 100 nF +/-10% 50 V 0603" CAPC1608X90X40NL10T20 925.39,2550 r0 top value=100nF
C71 "Capacitor 1uF 10%, 50V, X7R, 1210" CAPC3225X270X30ML30 3120,1520 r90 top value=1uF
C72 "Capacitor 100 nF +/-10% 50 V 0603" CAPC1608X90X40NL10T20 3220,1520 r90 top value=100nF
C73 "Capacitor 100 nF +/-10% 50 V 0603" CAPC1608X90X40NL10T20 1400,11350 r90 bottom value=100nF
C74 "Capacitor 100 nF +/-10% 50 V 0603" CAPC1608X90X40NL10T20 1560,11350 r90 bottom value=100nF
C75 "Capacitor 100 nF +/-10% 50 V 0603" CAPC1608X90X40NL10T20 1720,11350 r90 bottom value=100nF
C76 "Capacitor 100 nF +/-10% 50 V 0603" CAPC1608X90X40NL10T20 1880,11350 r90 bottom value=100nF
C77 "Capacitor 100 nF +/-10% 50 V 0603" CAPC1608X90X40NL10T20 2040,11350 r90 bottom value=100nF
C78 "Capacitor 100 nF +/-10% 50 V 0603" CAPC1608X90X40NL10T20 2200,11350 r90 bottom value=100nF
C79 "Capacitor 100 nF +/-10% 50 V 0603" CAPC1608X90X40NL10T20 2360,11350 r90 bottom value=100nF
C80 "Capacitor 100 nF +/-10% 50 V 0603" CAPC1608X90X40NL10T20 2520,11350 r90 bottom value=100nF
C81 "Capacitor 2.2uF 10%, 50V, X7R, 0805" CAPC2013X95X50ML10T25 3010,11030 r0 bottom value=2.2uF
C82 "Capacitor 100 nF +/-10% 50 V 0603" CAPC1608X90X40NL10T20 2900,11120 r0 bottom value=100nF
C83 "Capacitor 100 nF +/-10% 50 V 0603" CAPC1608X90X40NL10T20 3030,11120 r0 bottom value=100nF
C84 "Capacitor 100 nF +/-10% 50 V 0603" CAPC1608X90X40NL10T20 3420,10820 r0 top value=100nF
C85 "Capacitor 100 nF +/-10% 50 V 0603" CAPC1608X90X40NL10T20 3630,10810 r0 top value=100nF
C86 "Capacitor 100 nF +/-10% 50 V 0603" CAPC1608X90X40NL10T20 3620,10960 r0 top value=100nF
C87 "Capacitor 100 nF +/-10% 50 V 0603" CAPC1608X90X40NL10T20 960,3270 r0 top value=100nF
C88 "Capacitor 100 nF +/-10% 50 V 0603" CAPC1608X90X40NL10T20 2520,5235 r270 top value=100nF
C89 "Capacitor 100 nF +/-10% 50 V 0603" CAPC1608X90X40NL10T20 3355,6305 r90 top value=100nF
C90A "Capacitor 100 nF +/-10% 50 V 0603" CAPC1608X90X40NL10T20 3675,3230 r180 bottom value=100nF (schematic designator C90)
C90B "Capacitor 100 nF +/-10% 50 V 0603" CAPC1608X90X40NL10T20 3695,7940 r180 bottom value=100nF (schematic designator C90)
C90C "Capacitor 100 nF +/-10% 50 V 0603" CAPC1608X90X40NL10T20 3680,5180 r180 bottom value=100nF (schematic designator C90)
C90D "Capacitor 100 nF +/-10% 50 V 0603" CAPC1608X90X40NL10T20 3721.16,10046 r180 bottom value=100nF (schematic designator C90)
C91A "Capacitor 1uF 10%, 50V, X7R, 1210" CAPC3225X270X30ML30 3695,3085 r90 bottom value=1uF (schematic designator C91)
C91B "Capacitor 1uF 10%, 50V, X7R, 1210" CAPC3225X270X30ML30 3715,7795 r90 bottom value=1uF (schematic designator C91)
C91C "Capacitor 1uF 10%, 50V, X7R, 1210" CAPC3225X270X30ML30 3700,5035 r90 bottom value=1uF (schematic designator C91)
C91D "Capacitor 1uF 10%, 50V, X7R, 1210" CAPC3225X270X30ML30 3741.16,9901 r90 bottom value=1uF (schematic designator C91)
C92A "Capacitor 1uF 10%, 50V, X7R, 1210" CAPC3225X270X30ML30 3580,2785 r180 bottom value=1uF (schematic designator C92)
C92B "Capacitor 1uF 10%, 50V, X7R, 1210" CAPC3225X270X30ML30 3600,7495 r180 bottom value=1uF (schematic designator C92)
C92C "Capacitor 1uF 10%, 50V, X7R, 1210" CAPC3225X270X30ML30 3585,4735 r180 bottom value=1uF (schematic designator C92)
C92D "Capacitor 1uF 10%, 50V, X7R, 1210" CAPC3225X270X30ML30 3626.16,9601 r180 bottom value=1uF (schematic designator C92)
C93A "Capacitor 100 nF +/-10% 50 V 0603" CAPC1608X90X40NL10T20 3675,2940 r180 bottom value=100nF (schematic designator C93)
C93B "Capacitor 100 nF +/-10% 50 V 0603" CAPC1608X90X40NL10T20 3695,7650 r180 bottom value=100nF (schematic designator C93)
C93C "Capacitor 100 nF +/-10% 50 V 0603" CAPC1608X90X40NL10T20 3680,4890 r180 bottom value=100nF (schematic designator C93)
C93D "Capacitor 100 nF +/-10% 50 V 0603" CAPC1608X90X40NL10T20 3721.16,9756 r180 bottom value=100nF (schematic designator C93)
D1A "BZX84-C10,215" FP-SOT23-IPC_A 1646.6,3727.6 r180 top (schematic designator D1)
D1B "BZX84-C10,215" FP-SOT23-IPC_A 1646.6,7388.07 r180 top (schematic designator D1)
D1C "BZX84-C10,215" FP-SOT23-IPC_A 1646.6,6897.6 r180 top (schematic designator D1)
D1D "BZX84-C10,215" FP-SOT23-IPC_A 1646.6,4938.07 r180 top (schematic designator D1)
D1E "BZX84-C10,215" FP-SOT23-IPC_A 1645,6360 r180 top (schematic designator D1)
D1F "BZX84-C10,215" FP-SOT23-IPC_A 1646.6,5650 r180 top (schematic designator D1)
DC1 "V375C24C150BL" V375C24C150BL-Footprint-1 4250,3050 r270 top locked
DC2 "V375C24C150BL" V375C24C150BL-Footprint-1 4250,5000 r270 top locked
DC3 "V375C24C150BL" V375C24C150BL-Footprint-1 4250,7750 r270 top locked
DC4 "V375C24C150BL" V375C24C150BL-Footprint-1 4250,9700 r270 top locked
DC5 "REM30-2424SW" REM30-2424SW-Footprint-1 2405,9030 r90 top
FB1 "BLM18SG121TN1D" FP-BLM18-0_15-t0_5-d1_2-IPC_B 6750,11426.62 r90 top
FB2 "BLM18SG121TN1D" FP-BLM18-0_15-t0_5-d1_2-IPC_B 6753.99,561.89 r270 top
J1 "ESQ-132-14-G-D" SMTC-ESQ-132-14-X-D 4000,11600 r180 top
J2 "ESQ-132-14-G-D" SMTC-ESQ-132-14-X-D 4000,300 r180 top locked
J3 "M80-5000000M5-02-333-00-000" FP-M80-5000000M5-02-333-0-MFG 6555,4640 r90 top
J4 "M80-5000000M5-02-333-00-000" FP-M80-5000000M5-02-333-0-MFG 6555,8950 r90 top
J5 "M80-5400642" FP-M80-5400642-MFG 414.65,10043.46 r270 top
J6 "M80-5400442" M80-5400442-Footprint-1 579.37,9280.63 r270 top
J7 "M80-5400442" M80-5400442-Footprint-1 579.37,2774.37 r270 top
J8 "M80-5400442" M80-5400442-Footprint-1 579.37,5324.37 r270 top
J9 "M80-5400442" M80-5400442-Footprint-1 579.37,2129.37 r270 top
J10 "M80-5401442" M80-5401442-Footprint-1 415,11005 r270 top
J11 "M80-5400442" M80-5400442-Footprint-1 580,6027.83 r270 top
J12 "M80-5400442" M80-5400442-Footprint-1 584.37,1459.37 r270 top
J13 "M80-5400442" M80-5400442-Footprint-1 579.37,4620.63 r270 top
J14 "M80-5400442" M80-5400442-Footprint-1 580,777.17 r270 top
J15 "M80-5400442" M80-5400442-Footprint-1 579.37,3470.63 r270 top
J16 "M80-5400442" M80-5400442-Footprint-1 579.37,6729.37 r270 top
J17 "M80-5400442" M80-5400442-Footprint-1 579.37,7429.37 r270 top
J18 "M80-5400442" M80-5400442-Footprint-1 579.37,8615.63 r270 top
J19 "5002" FP-5002-MFG 5575,4670 r0 top
J20 "5002" FP-5002-MFG 5865,4905 r0 top
J21 "5002" FP-5002-MFG 6100,9100 r0 top
J22 "5002" FP-5002-MFG 5695,8725 r0 top
J23 "5002" FP-5002-MFG 3045,4025 r0 top
J24 "5002" FP-5002-MFG 2760,3340 r0 top
J25 "5002" FP-5002-MFG 2770,5000 r0 top
J26 "5002" FP-5002-MFG 2900,6710 r0 top
J27 "5002" FP-5002-MFG 2795,7700 r0 top
J28 "5002" FP-5002-MFG 3005,10135 r0 top
J29 "5002" FP-5002-MFG 1765,9950 r0 top
J30 "5002" FP-5002-MFG 890,9975 r0 top
J31 "5002" FP-5002-MFG 1630,10565 r0 top
J32 "5002" FP-5002-MFG 1980,5725 r0 top
J33 "5002" FP-5002-MFG 2055,6485 r0 top
J34 "5002" FP-5002-MFG 2030,5095 r0 top
J35 "5002" FP-5002-MFG 2050,3895 r0 top
J36 "5002" FP-5002-MFG 1525,10305 r0 top
J37 "5002" FP-5002-MFG 880,8965 r0 top
J38 "5002" FP-5002-MFG 805,10605 r0 top
J39 "5002" FP-5002-MFG 855,9610 r0 top
J40 "5002" FP-5002-MFG 4040,1655 r0 top
J41 "5002" FP-5002-MFG 2745,11370 r0 top
J42 "5002" FP-5002-MFG 3265,11375 r0 top
L1 "DLW5BTM101SQ2L" FP-DLW5BT-MFG 2190,7840 r180 top
L2 "74404084120" "WE-LQS 8040" 2420,10760 r180 top value=12uH
L3 "74404084120" "WE-LQS 8040" 1750,2860 r0 top value=12uH
MH1 "MH-MARS2-6-32" "MH-M3-Footprint-1 - Oversized MARS2" 250,250 r180 top locked
MH2 "MH-MARS2-6-32" "MH-M3-Footprint-1 - Oversized MARS2" 4500,250 r180 top locked
MH3 "MH-MARS2-6-32" "MH-M3-Footprint-1 - Oversized MARS2" 6750,250 r180 top locked
MH4 "MH-MARS2-6-32" "MH-M3-Footprint-1 - Oversized MARS2" 6750,4000 r180 top locked
MH5 "MH-MARS2-6-32" "MH-M3-Footprint-1 - Oversized MARS2" 6750,8000 r180 top locked
MH6 "MH-MARS2-6-32" "MH-M3-Footprint-1 - Oversized MARS2" 6750,11750 r180 top locked
MH7 "MH-MARS2-6-32" "MH-M3-Footprint-1 - Oversized MARS2" 4500,11750 r180 top locked
MH8 "MH-MARS2-6-32" "MH-M3-Footprint-1 - Oversized MARS2" 250,11750 r180 top locked
MH9 "MH-MARS2-6-32" "MH-M3-Footprint-1 - Oversized MARS2" 250,8000 r180 top locked
MH10 "MH-MARS2-6-32" "MH-M3-Footprint-1 - Oversized MARS2" 250,4000 r180 top locked
MH11 "MH-MARS2-6-32" "MH-M3-Footprint-1 - Oversized MARS2" 3500,6000 r180 top locked
Q1 "STD85N10F7AG" TO228P970-3N 2690.55,5650 r180 top
Q2 "STD85N10F7AG" TO228P970-3N 2690,6190 r180 top
Q3A "IRFR5410TRPBF" FP-PG-TO252-3-MFG 1290,3560 r90 top (schematic designator Q3)
Q3B "IRFR5410TRPBF" FP-PG-TO252-3-MFG 1290,7220 r90 top (schematic designator Q3)
Q3C "IRFR5410TRPBF" FP-PG-TO252-3-MFG 1290,6730 r90 top (schematic designator Q3)
Q3D "IRFR5410TRPBF" FP-PG-TO252-3-MFG 1271.54,4770 r90 top (schematic designator Q3)
Q3E "IRFR5410TRPBF" FP-PG-TO252-3-MFG 1290,6190 r90 top (schematic designator Q3)
Q3F "IRFR5410TRPBF" FP-PG-TO252-3-MFG 1291.54,5480 r90 top (schematic designator Q3)
Q4A "MMBT2222AM3T5G" ROHM-SOT723-3_V 1725,3530 r180 top (schematic designator Q4)
Q4B "MMBT2222AM3T5G" ROHM-SOT723-3_V 1725,7185.75 r180 top (schematic designator Q4)
Q4C "MMBT2222AM3T5G" ROHM-SOT723-3_V 1725,6710 r180 top (schematic designator Q4)
Q4D "MMBT2222AM3T5G" ROHM-SOT723-3_V 1725,4740 r180 top (schematic designator Q4)
Q4E "MMBT2222AM3T5G" ROHM-SOT723-3_V 1725,6160 r180 top (schematic designator Q4)
Q4F "MMBT2222AM3T5G" ROHM-SOT723-3_V 1725,5450 r180 top (schematic designator Q4)
R1 "Resistor 75R0 +/-1% 0603 100 mW" RESC1609X50X30ML08T20 5530,3692.44 r270 bottom value=75
R6 "Resistor 75R0 +/-1% 0603 100 mW" RESC1609X50X30ML08T20 5520,5690 r270 bottom value=75
R11 "Resistor 49K9 +/-1% 0603 100 mW" RESC1608X55X25ML10T15 3250,3250 r90 bottom value=49.9k
R12 "Resistor 0R +/- 5% 0603 100 mW" RESC1608X55X25ML10T15 6400,6509.53 r90 bottom value=0
R13 "Resistor 0R +/- 5% 0603 100 mW" RESC1608X55X25ML10T15 6280,6509.53 r90 bottom value=0
R14 "Resistor 75R0 +/-1% 0603 100 mW" RESC1609X50X30ML08T20 5565,8455 r180 bottom value=75
R15 "Resistor 0R01 1% 1206 1W" FP-WSLP1206-FP_1_65x1_93x-IPC_A 2770,5860 r180 top
R16 "Resistor 49K9 +/-1% 0603 100 mW" RESC1608X55X25ML10T15 3250,5180 r90 bottom value=49.9k
R17 "Resistor 75R0 +/-1% 0603 100 mW" RESC1609X50X30ML08T20 5580,10385 r180 bottom value=75
R18 "Resistor 0R01 1% 1206 1W" FP-WSLP1206-FP_1_65x1_93x-IPC_A 2769.96,6420 r180 top
R19 "Resistor 0R01 1% 1206 1W" FP-WSLP1206-FP_1_65x1_93x-IPC_A 2278.84,5920 r180 top
R20 "Resistor 56K2 +/-1% 0603 100 mW" RESC1608X55X25ML10T15 1190,2720 r90 top value=56.2k
R21 "Resistor 49K9 +/-1% 0603 100 mW" RESC1608X55X25ML10T15 3250,7940 r90 bottom value=49.9k
R22 "Resistor 51R1 +/-1% 0603 100 mW" RESC1609X50X30ML08T20 2880,622 r270 top value=51.1
R23 "Resistor 51R1 +/-1% 0603 100 mW" RESC1609X50X30ML08T20 3080,622.44 r270 top value=51.1
R24 "Resistor 10k +/-1% 0603 100 mW" RESC1608X55X25ML10T15 1190,2570 r90 top value=10k
R25 "Resistor 49K9 +/-1% 0603 100 mW" RESC1608X55X25ML10T15 3250,9900 r90 bottom value=49.9k
R26 "Resistor 0R033 1% 1206 1W" RESC3216X70X50NL05T20 1780,7770 r180 top
R27 "Resistor 100K +/-1% 0603 100 mW" RESC1609X50X30ML08T20 2530,10090 r0 bottom value=100K
R28 "Resistor 51R1 +/-1% 0603 100 mW" RESC1609X50X30ML08T20 3480,620 r270 top value=51.1
R29 "Resistor 931K +/-1% 0603 100 mW" RESC1609X50X30ML08T20 2390,10090 r0 bottom value=931K
R30 "Resistor 1R0 1% 2512 1W" FP-CRCW2512-e3-MFG 2410,10340 r90 top
R31 "Resistor 0R033 1% 1206 1W" RESC3216X70X50NL05T20 2730,2830 r180 top
R32 "Resistor 1R0 1% 2512 1W" FP-CRCW2512-e3-MFG 2040,2710 r90 top
R33 "Resistor 10k +/-1% 0603 100 mW" RESC1608X55X25ML10T15 2570,2610 r0 top value=10k
R34 "Resistor 51R1 +/-1% 0603 100 mW" RESC1609X50X30ML08T20 2490,625 r270 top value=51.1
R35 "Resistor 51R1 +/-1% 0603 100 mW" RESC1609X50X30ML08T20 2680,622.56 r270 top value=51.1
R36 "Resistor 100k +/-1% 0603 100 mW" RESC1608X55X25ML10T15 2570,2520 r180 top value=100k
R37 "Resistor 0R033 1% 1206 1W" RESC3216X70X50NL05T20 870,5460 r0 top
R38 "Resistor 51R1 +/-1% 0603 100 mW" RESC1609X50X30ML08T20 4080,620 r270 top value=51.1
R39 "Resistor 0R033 1% 1206 1W" RESC3216X70X50NL05T20 890,6170 r0 top
R40 "Resistor 51R1 +/-1% 0603 100 mW" RESC1609X50X30ML08T20 3880,620 r270 top value=51.1
R41 "Resistor 0R033 1% 1206 1W" RESC3216X70X50NL05T20 876.1,4660.83 r0 top
R42 "Resistor 51R1 +/-1% 0603 100 mW" RESC1609X50X30ML08T20 3680,620 r270 top value=51.1
R43 "Jumper 0603" RESC0603(1608)_L 1330,6940 r180 top value=0
R44 "Jumper 0603" RESC0603(1608)_L 1467.56,6940 r0 top value=0
R45 "Resistor 0R033 1% 1206 1W" RESC3216X70X50NL05T20 960,3570 r0 top
R46 "Resistor 51R1 +/-1% 0603 100 mW" RESC1609X50X30ML08T20 870,610 r0 top value=51.1
R47 "Jumper 0603" RESC0603(1608)_L 1330,7460 r180 top value=0
R48 "Jumper 0603" RESC0603(1608)_L 1467.56,7460 r0 top value=0
R49 "Resistor 0R01 1% 1206 1W" FP-WSLP1206-FP_1_65x1_93x-IPC_A 930,2860 r180 top
R50 "Resistor 51R1 +/-1% 0603 100 mW" RESC1609X50X30ML08T20 3280,620 r270 top value=51.1
R51 "Resistor 51R1 +/-1% 0603 100 mW" RESC1609X50X30ML08T20 1960,11360 r270 bottom value=51.1
R52 "Resistor 51R1 +/-1% 0603 100 mW" RESC1609X50X30ML08T20 1800,11360 r270 bottom value=51.1
R53 "Resistor 51R1 +/-1% 0603 100 mW" RESC1609X50X30ML08T20 1640,11360 r270 bottom value=51.1
R54 "Resistor 51R1 +/-1% 0603 100 mW" RESC1609X50X30ML08T20 1480,11360 r270 bottom value=51.1
R55 "Resistor 51R1 +/-1% 0603 100 mW" RESC1609X50X30ML08T20 1320,11360 r270 bottom value=51.1
R56 "Resistor 7K15 +/-1% 0603 100 mW" RESC1609X50X30ML08T20 840,11340 r180 bottom value=7.15k
R57 "Resistor 7K15 +/-1% 0603 100 mW" RESC1609X50X30ML08T20 842.44,11240 r180 bottom value=7.15k
R58 "Resistor 7K15 +/-1% 0603 100 mW" RESC1609X50X30ML08T20 840,11130 r180 bottom value=7.15k
R59 "Resistor 7K15 +/-1% 0603 100 mW" RESC1609X50X30ML08T20 840,11030 r180 bottom value=7.15k
R60 "Resistor 7K15 +/-1% 0603 100 mW" RESC1609X50X30ML08T20 4050,6385 r0 top value=7.15k
R61 "Resistor 51R1 +/-1% 0603 100 mW" RESC1609X50X30ML08T20 2440,11360 r270 bottom value=51.1
R62 "Resistor 51R1 +/-1% 0603 100 mW" RESC1609X50X30ML08T20 2280,11360 r270 bottom value=51.1
R63 "Resistor 51R1 +/-1% 0603 100 mW" RESC1609X50X30ML08T20 2120,11360 r270 bottom value=51.1
R64 "Resistor 7K15 +/-1% 0603 100 mW" RESC1609X50X30ML08T20 840,10930 r180 bottom value=7.15k
R65 "Resistor 7K15 +/-1% 0603 100 mW" RESC1609X50X30ML08T20 840,10830 r180 bottom value=7.15k
R66 "Resistor 7K15 +/-1% 0603 100 mW" RESC1609X50X30ML08T20 840,10720 r180 bottom value=7.15k
R67 "Resistor 4k7 +/-1% 0603 100 mW" RESC1608X55X25ML10T15 3300,10600 r270 top value=4.7k
R68 "Resistor 4k7 +/-1% 0603 100 mW" RESC1608X55X25ML10T15 3300,10730.47 r90 top value=4.7k
R69A "Resistor 100k +/-1% 0603 100 mW" RESC1608X55X25ML10T15 1570,3560 r270 top value=100k (schematic designator R69)
R69B "Resistor 100k +/-1% 0603 100 mW" RESC1608X55X25ML10T15 1570,7220.47 r270 top value=100k (schematic designator R69)
R69C "Resistor 100k +/-1% 0603 100 mW" RESC1608X55X25ML10T15 1570,6730 r270 top value=100k (schematic designator R69)
R69D "Resistor 100k +/-1% 0603 100 mW" RESC1608X55X25ML10T15 1570,4770.47 r270 top value=100k (schematic designator R69)
R69E "Resistor 100k +/-1% 0603 100 mW" RESC1608X55X25ML10T15 1570,6190.47 r270 top value=100k (schematic designator R69)
R69F "Resistor 100k +/-1% 0603 100 mW" RESC1608X55X25ML10T15 1570,5480 r270 top value=100k (schematic designator R69)
R70A "Resistor 10k +/-1% 0603 100 mW" RESC1608X55X25ML10T15 1830,3600 r180 top value=10k (schematic designator R70)
R70B "Resistor 10k +/-1% 0603 100 mW" RESC1608X55X25ML10T15 1830,7250 r180 top value=10k (schematic designator R70)
R70C "Resistor 10k +/-1% 0603 100 mW" RESC1608X55X25ML10T15 1830,6770 r180 top value=10k (schematic designator R70)
R70D "Resistor 10k +/-1% 0603 100 mW" RESC1608X55X25ML10T15 1830,4810 r180 top value=10k (schematic designator R70)
R70E "Resistor 10k +/-1% 0603 100 mW" RESC1608X55X25ML10T15 1830,6250 r180 top value=10k (schematic designator R70)
R70F "Resistor 10k +/-1% 0603 100 mW" RESC1608X55X25ML10T15 1830,5520 r180 top value=10k (schematic designator R70)
R71A "Resistor 10k +/-1% 0603 100 mW" RESC1608X55X25ML10T15 1830,3510 r180 top value=10k (schematic designator R71)
R71B "Resistor 10k +/-1% 0603 100 mW" RESC1608X55X25ML10T15 1830,7160 r180 top value=10k (schematic designator R71)
R71C "Resistor 10k +/-1% 0603 100 mW" RESC1608X55X25ML10T15 1830,6680 r180 top value=10k (schematic designator R71)
R71D "Resistor 10k +/-1% 0603 100 mW" RESC1608X55X25ML10T15 1830,4720 r180 top value=10k (schematic designator R71)
R71E "Resistor 10k +/-1% 0603 100 mW" RESC1608X55X25ML10T15 1830,6160 r180 top value=10k (schematic designator R71)
R71F "Resistor 10k +/-1% 0603 100 mW" RESC1608X55X25ML10T15 1830,5430 r180 top value=10k (schematic designator R71)
R72 "Resistor 4k7 +/-1% 0603 100 mW" RESC1608X55X25ML10T15 3480,11110 r180 top value=4.7k
R73 "Resistor 4k7 +/-1% 0603 100 mW" RESC1608X55X25ML10T15 3480,11030 r180 top value=4.7k
R74 "Resistor 4k7 +/-1% 0603 100 mW" RESC1608X55X25ML10T15 3480,11190 r180 top value=4.7k
R75 "Resistor 100R +/-1% 0603 100 mW" RESC1609X50X30ML08T20 2580.47,5115 r0 top value=100
R76 "Resistor 100R +/-1% 0603 100 mW" RESC1609X50X30ML08T20 3245,6340 r0 top value=100
R77A "Resistor 10k +/-1% 0603 100 mW" RESC1608X55X25ML10T15 1829.53,3725 r180 top value=10k (schematic designator R77)
R77B "Resistor 10k +/-1% 0603 100 mW" RESC1608X55X25ML10T15 1860.47,7400 r0 top value=10k (schematic designator R77)
R77C "Resistor 10k +/-1% 0603 100 mW" RESC1608X55X25ML10T15 1870,6900 r0 top value=10k (schematic designator R77)
R77D "Resistor 10k +/-1% 0603 100 mW" RESC1608X55X25ML10T15 1875.47,4960 r0 top value=10k (schematic designator R77)
R77E "Resistor 10k +/-1% 0603 100 mW" RESC1608X55X25ML10T15 1880,6375 r0 top value=10k (schematic designator R77)
R77F "Resistor 10k +/-1% 0603 100 mW" RESC1608X55X25ML10T15 1975,5330 r0 top value=10k (schematic designator R77)
R78A "Resistor 10k +/-1% 0603 100 mW" RESC1608X55X25ML10T15 1650,3560 r90 top value=10k (schematic designator R78)
R78B "Resistor 10k +/-1% 0603 100 mW" RESC1608X55X25ML10T15 1650,7220.47 r90 top value=10k (schematic designator R78)
R78C "Resistor 10k +/-1% 0603 100 mW" RESC1608X55X25ML10T15 1650,6730 r90 top value=10k (schematic designator R78)
R78D "Resistor 10k +/-1% 0603 100 mW" RESC1608X55X25ML10T15 1650,4770.47 r90 top value=10k (schematic designator R78)
R78E "Resistor 10k +/-1% 0603 100 mW" RESC1608X55X25ML10T15 1650,6190.47 r90 top value=10k (schematic designator R78)
R78F "Resistor 10k +/-1% 0603 100 mW" RESC1608X55X25ML10T15 1650,5480 r90 top value=10k (schematic designator R78)
SY "6LYR_STACK" 6LYR_STACK-Footprint-1 6905,1410 r90 top
T1 "29768" 29768-Footprint-1 6040,3520 r0 top
T2 "29768" 29768-Footprint-1 6040,5520 r0 top
T3 "29768" 29768-Footprint-1 6040,8250 r0 top
T4 "29768" 29768-Footprint-1 6040,10180 r0 top
TP1 "5005" TestPoint-5005-Footprint-1 1415,7785 r0 top
TP2 "5005" TestPoint-5005-Footprint-1 1438.16,1741.72 r0 top
TP3 "5003" KSTN-5003 3005,10810 r0 top
TP4 "5001" FP-5001-MFG 1070,1090 r0 top
TP5 "5001" FP-5001-MFG 1070,1395 r0 top
TP6 "5001" FP-5001-MFG 4100,10625 r0 top
TP7 "5001" FP-5001-MFG 3870,10625 r0 top
TP8 "5001" FP-5001-MFG 2605,6575 r0 top
TP9 "5001" FP-5001-MFG 2375,6575 r0 top
U1A "REF35102QDBVR" SOT95P280X145-6M 3515,3150 r0 bottom (schematic designator U1)
U1B "REF35102QDBVR" SOT95P280X145-6M 3535,7860 r0 bottom (schematic designator U1)
U1C "REF35102QDBVR" SOT95P280X145-6M 3520,5100 r0 bottom (schematic designator U1)
U1D "REF35102QDBVR" SOT95P280X145-6M 3561.16,9966 r0 bottom (schematic designator U1)
U2A "TLV3601QDBVRQ1" SOT95P280X145-5M 3515,2985 r0 bottom (schematic designator U2)
U2B "TLV3601QDBVRQ1" SOT95P280X145-5M 3535,7695 r0 bottom (schematic designator U2)
U2C "TLV3601QDBVRQ1" SOT95P280X145-5M 3520,4935 r0 bottom (schematic designator U2)
U2D "TLV3601QDBVRQ1" SOT95P280X145-5M 3561.16,9801 r0 bottom (schematic designator U2)
U5 "LTC4357HMS8#PBF" LT-MS8-8_N 2700,5235 r180 top
U6 "MAX4173FEUT+T" MAXM-U6+1_N 2280,5650 r90 top
U7 "LTC4357HMS8#PBF" LT-MS8-8_N 3140,6180 r0 top
U8 "MAX4173HEUT+T" MAXM-U6+1_N 1780,7950 r270 top
U9 "R-78E5.0-0.5" REPO-R-78E-0.5-3_V 2050,10470 r180 top
U10 "R-785.0-0.5" REPO-R-78XX-3_V 2380,2830 r0 top
U11 "MAX4173HEUT+T" MAXM-U6+1_N 2750,2990 r270 top
U12 "MAX4173HEUT+T" MAXM-U6+1_N 860,5310 r90 top
U13 "MAX4173HEUT+T" MAXM-U6+1_N 880,6020 r90 top
U14 "MAX4173HEUT+T" MAXM-U6+1_N 866.1,4500.83 r90 top
U15 "MAX4173HEUT+T" MAXM-U6+1_N 950,3400 r90 top
U16 "MAX3221EAE+" FP-A16-2-IPC_C 1140,10390 r0 top
U17 "MAX3221EAE+" FP-A16-2-IPC_C 1130,9270 r0 top
U18 "ADUM2201ARWZ" ADI-RW-16_M 1325,9887.91 r90 top
U19 "MAX4173FEUT+T" MAXM-U6+1_N 910,2680 r90 top
U20 "SN74HC151QDRQ1" D0016A_M 3420,1720 r180 top
U21 "AD590KF" FP-F-2-MFG 4300,6415 r270 top
U22 "BME280" FP-BME280-MFG 2980,11280 r90 bottom
U23 "TCA9534ADWR" FP-DW0016A-IPC_C 3824.19,11215 r180 top
U24 "ADUM1250ARZ-RL7" ADI-R-8_N 3550,10670 r0 top

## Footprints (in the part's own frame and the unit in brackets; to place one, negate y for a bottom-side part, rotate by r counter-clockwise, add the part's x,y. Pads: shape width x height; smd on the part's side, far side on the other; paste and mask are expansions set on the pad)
6LYR_STACK-Footprint-1 [mil]
  Keep-Out Layer region: -180,-30 190,-30 190,35 -180,35
  silkscreen extent -185,-35 195,40
29768-Footprint-1 [mil]
  round 65 hole 40: 1(-300,-200) 2(-300,-100) 3(-300,100) 4(-300,200) 5(300,100) 6(300,-100)
  silkscreen extent -350,-250 350,250, body extent -350,-250 350,250, height 360
ADI-R-8_N [mm] "SOIC, 8-Leads, Body 5x4mm, Pitch 1.27mm, IPC Medium Density"
  oval 1.45x0.6 smd: 1(-2.725,1.905) 2(-2.725,0.635) 3(-2.725,-0.635) 4(-2.725,-1.905) 5(2.725,-1.905) 6(2.725,-0.635) 7(2.725,0.635) 8(2.725,1.905)
  silkscreen extent -2.85,-2.5 1.6,2.88, body extent -3,-2.5 3,2.5, height 1.75
ADI-RW-16_M [mm] "SOIC, 16-Leads, Body 10.3x7.5mm, Pitch 1.27mm, IPC Low Density"
  oval 2.6x0.7 smd: 1(-4.625,4.445) 2(-4.625,3.175) 3(-4.625,1.905) 4(-4.625,0.635) 5(-4.625,-0.635) 6(-4.625,-1.905) 7(-4.625,-3.175) 8(-4.625,-4.445) 9(4.625,-4.445) 10(4.625,-3.175) 11(4.625,-1.905) 12(4.625,-0.635) 13(4.625,0.635) 14(4.625,1.905) 15(4.625,3.175) 16(4.625,4.445)
  silkscreen extent -4.75,-5.25 2.93,5.47, body extent -3.8,-5.25 3.8,5.25, height 2.65
CAPC0603(1608)100_L [mm] "Chip Capacitor, Body 1.6x0.8mm, Height 1.0mm, IPC High Density"
  rrect25% 0.66x0.76 smd: 1(-0.7,0) 2(0.7,0)
  silkscreen extent 0,-0.3 0,0.3, body extent -0.8,-0.4 0.8,0.4, height 0.95
CAPC1608X90X40NL10T20 [mm] "Chip Capacitor, 2-Leads, Body 1.70x0.90mm, IPC Medium Density"
  rect 0.95x0.95 smd: 1(-0.625,0) 2(0.625,0)
  body extent -0.85,-0.45 0.85,0.45, height 0.9
CAPC2013X95X50ML10T25 [mm] "Chip Capacitor, 2-Leads, Body 2.10x1.35mm, IPC Low Density"
  rect 1.45x1.5 smd: 1(-0.925,0) 2(0.925,0)
  body extent -1.05,-0.67 1.05,0.67, height 0.95
CAPC2013X145X50NL20T25 [mm] "Chip Capacitor, 2-Leads, Body 2.00x1.25mm, IPC Medium Density"
  rect 1.3x1.45 smd: 1(-0.8,0) 2(0.8,0)
  body extent -1.1,-0.72 1.1,0.72, height 1.45
CAPC3225X270X30ML30 [mm] "Chip Capacitor, 2-Leads, Body 3.5x2.7mm, IPC Low Density"
  rect 1.15x2.8 smd: 1(-1.725,0) 2(1.725,0)
  silkscreen extent -0.75,-1.3 0.75,1.3, body extent -1.75,-1.35 1.75,1.35, height 2.7
D0016A_M [mm] "SOIC, 16-Leads, Body 10x4mm, Pitch 1.27mm, IPC Low Density"
  rrect15% 1.65x0.65 smd: 1(-2.825,4.445) 2(-2.825,3.175) 3(-2.825,1.905) 4(-2.825,0.635) 5(-2.825,-0.635) 6(-2.825,-1.905) 7(-2.825,-3.175) 8(-2.825,-4.445) 9(2.825,-4.445) 10(2.825,-3.175) 11(2.825,-1.905) 12(2.825,-0.635) 13(2.825,0.635) 14(2.825,1.905) 15(2.825,3.175) 16(2.825,4.445)
  silkscreen extent -2.95,-5 1.6,5.44, body extent -3,-4.95 3,4.95, height 1.59
FP-5001-MFG [mm]
  round 1.57 hole 1.016: 1(0,0)
  silkscreen extent -1.35,-1.34 1.35,1.34, body extent -1.45,-1.45 1.45,1.45, height 0.25
FP-5002-MFG [mm]
  round 1.57 hole 1.02 paste-1000 mask+0: 1(0,0)
  silkscreen extent -1.35,-1.34 1.35,1.34, body extent -1.45,-1.45 1.45,1.45, height 0.25
FP-A16-2-IPC_C [mm]
  rect 1.482x0.418 smd paste+0 mask+0: 1(-3.364,2.275)
  rrect100% 1.482x0.418 smd paste+0 mask+0: 2(-3.364,1.625) 3(-3.364,0.975) 4(-3.364,0.325) 5(-3.364,-0.325) 6(-3.364,-0.975) 7(-3.364,-1.625) 8(-3.364,-2.275) 9(3.364,-2.275) 10(3.364,-1.625) 11(3.364,-0.975) 12(3.364,-0.325) 13(3.364,0.325) 14(3.364,0.975) 15(3.364,1.625) 16(3.364,2.275)
  silkscreen extent -4.88,-3.1 2.12,3.1, body extent -4.2,-3.2 4.2,3.2, height 0.25
FP-BLM18-0_15-t0_5-d1_2-IPC_B [mil]
  rect 43.55x37.73 smd paste+0 mask+0: 1(-26.62,0) 2(26.62,0)
  silkscreen extent -48,-35 48,35, body extent -58,-29 58,29, height 10
FP-BME280-MFG [mm]
  rect 0.5x0.35 smd paste+0 mask+0: 1(1.025,0.975) 2(1.025,0.325) 3(1.025,-0.325) 4(1.025,-0.975) 5(-1.025,-0.975) 6(-1.025,-0.325) 7(-1.025,0.325) 8(-1.025,0.975)
  silkscreen extent -1.3,-1.55 1.97,1.55
FP-CRCW2512-e3-MFG [mm]
  rect 1.45x3.5 smd paste+0 mask+0: 1(-3.1,0) 2(3.1,0)
  silkscreen extent -2,-1.65 2,1.65, body extent -3.93,-1.85 3.93,1.85, height 0.25
FP-DLW5BT-MFG [mil]
  round 34.99 smd paste+0 mask+0: 1(-37.16,-71.6) 4(-37.16,54.87)
  round 35.31 smd paste+0 mask+0: 2(38.63,-71.6) 3(38.63,71.6)
  Top Layer region: 108.27,-92.52 17.72,-92.52 17.72,-25.59 57.09,-25.59 57.09,-64.96 108.27,-64.96 108.27,-92.52
  Top Layer region: -108.27,-92.52 -17.72,-92.52 -17.72,-25.59 -57.09,-25.59 -57.09,-64.96 -108.27,-64.96 -108.27,-92.52
  Top Layer region: 108.27,92.52 17.72,92.52 17.72,25.59 57.09,25.59 57.09,64.96 108.27,64.96 108.27,92.52
  Top Layer region: -108.27,92.52 -17.72,92.52 -17.72,25.59 -57.09,25.59 -57.09,64.96 -108.27,64.96 -108.27,92.52
  silkscreen extent -104,-126 104,104, body extent -112,-108 112,108, height 10
FP-DW0016A-IPC_C [mil]
  rect 78.85x21.34 smd paste+0 mask+0: 1(-175.81,175)
  rrect100% 78.85x21.34 smd paste+0 mask+0: 2(-175.81,125) 3(-175.81,75) 4(-175.81,25) 5(-175.81,-25) 6(-175.81,-75) 7(-175.81,-125) 8(-175.81,-175) 9(175.81,-175) 10(175.81,-125) 11(175.81,-75) 12(175.81,-25) 13(175.81,25) 14(175.81,75) 15(175.81,125) 16(175.81,175)
  silkscreen extent -240,-203 117,203, body extent -219,-207 219,207, height 10
FP-F-2-MFG [mil]
  rect 19x60 smd paste+0 mask+0: 1(-25,-140) 2(25,-140)
  silkscreen extent -46,-197 46,120, body extent -44,-165 44,115, height 50
FP-M80-5000000M5-02-333-0-MFG [mm]
  rect 2.5x2.5 hole 1.65 paste-1000 mask+0: A(2,1.8)
  round 2.5 hole 1.65 paste-1000 mask+0: B(-2,1.8)
  round 3.4 hole 2.25 paste-1000 mask+0: MT1(-6.5,2.8) MT2(6.5,2.8)
  silkscreen extent -9.25,-4.4 9.25,5.2, body extent -9.35,-4.5 9.35,4.6, height 0.25
FP-M80-5400642-MFG [mm]
  rect 1.2x1.2 hole 0.7 paste-1000 mask+0: 1(2,5.2)
  round 1.2 hole 0.7 paste-1000 mask+0: 2(0,5.2) 3(-2,5.2) 4(2,3.2) 5(0,3.2) 6(-2,3.2)
  round 2.25 hole 2.25 unplated paste-1000 mask+0: MT1(-5.5,4.2) MT2(5.5,4.2)
  silkscreen extent -8.5,-2.8 8.5,6.48, body extent -8.6,-2.9 8.6,5.9, height 0.25
FP-PG-TO252-3-MFG [mm]
  rect 1.5x2.5 smd paste+0 mask+0: 1(-2.3,-4.575) 3(2.3,-4.575)
  rect 7x7 smd paste+0 mask+0: 4(0,2.325)
  silkscreen extent -3.36,-2.28 3.36,-1.55, body extent -3.6,-5.92 3.6,5.92, height 0.25
FP-RDEUE1+0_5-MFG [mm]
  rect 1.2x1.2 hole 0.7 paste-1000 mask+0: 1(-2.5,0)
  round 1.2 hole 0.7 paste-1000 mask+0: 2(2.5,0)
  silkscreen extent -3.85,-2 3.85,2, body extent -3.95,-2.1 3.95,2.1, height 0.25
FP-SOT23-IPC_A [mm]
  rect 1.655x0.602 smd paste+0 mask+0: 1(-0.975,0.95)
  rrect100% 1.655x0.602 smd paste+0 mask+0: 2(-0.975,-0.95) 3(0.975,0)
  silkscreen extent 0,-1.45 0.65,1.45, body extent -2.3,-1.95 2.3,1.95, height 0.25
FP-WSLP1206-FP_1_65x1_93x-IPC_A [mil]
  rect 61.81x77.12 smd paste+0 mask+0: 1(-58.84,0) 2(58.84,0)
  silkscreen extent -16,-39 16,39, body extent -109,-58 109,58, height 10
KEMT-D-7343-31-2_L [mm] "Molded TAN Capacitor, 2-Leads, Body 7.6x4.6mm, IPC High Density"
  rect 2.2x2.35 smd: 1(-2.925,0) 2(2.925,0)
  silkscreen extent -4.52,-2.3 3.8,2.3, body extent -3.8,-2.3 3.8,2.3, height 3.1
KSTN-5003 [mm] "Test Point, Through Hole, Dia 2.54mm"
  round 1.5 hole 1: 1(0,0)
  silkscreen extent -1.27,-1.27 1.27,1.27, body extent -1.27,-1.27 1.27,1.27, height 4.57
LT-MS8-8_N [mm] "SOP, 8-Leads, Body 3.1x3.1mm, Pitch 0.65mm, IPC Medium Density"
  oval 1.6x0.45 smd: 1(-2.15,0.975) 2(-2.15,0.325) 3(-2.15,-0.325) 4(-2.15,-0.975) 5(2.15,-0.975) 6(2.15,-0.325) 7(2.15,0.325) 8(2.15,0.975)
  silkscreen extent -2.28,-1.55 0.95,1.87, body extent -1.55,-1.55 1.55,1.55, height 1.1
M80-5400442-Footprint-1 [mm]
  rect 1.2x1.2 hole 0.7 paste-1000 mask+0: 1(1,1)
  round 1.2 hole 0.7 paste-1000 mask+0: 2(-1,1) 3(1,-1) 4(-1,-1)
  round 2.25 hole 2.25 unplated paste-1000 mask+0: MT1(-4.5,0) MT2(4.5,0)
  silkscreen extent -7,-7 7,2.63, body extent -7,-6.9 7,2.2, height 6.11
M80-5401442-Footprint-1 [mm]
  rect 1.2x1.2 hole 0.7 paste-1000 mask+0: 1(6,5.191)
  round 1.2 hole 0.7 paste-1000 mask+0: 2(4,5.191) 3(2,5.191) 4(0,5.191) 5(-2,5.191) 6(-4,5.191) 7(-6,5.191) 8(5.964,3.191) 9(3.964,3.191) 10(2.027,3.191) 11(0.027,3.191) 12(-1.973,3.191) 13(-3.937,3.175) 14(-6.024,3.142)
  round 2.25 hole 2.25 unplated paste-1000 mask+0: MT1(-9.5,4.191) MT2(9.5,4.191)
  silkscreen extent -12.5,-2.81 12.5,6.47, body extent -12,-2.8 12,6.3, height 6.08
MAXM-U6+1_N [mm] "SOT23, 6-Leads, Body 2.9x1.625mm, Pitch 0.95mm, IPC Medium Density"
  rect 1.1x0.6 smd: 1(-1.2,0.95) 2(-1.2,0) 3(-1.2,-0.95) 4(1.2,-0.95) 5(1.2,0) 6(1.2,0.95)
  silkscreen extent -1.32,-1.5 0.25,1.92, body extent -0.87,-1.5 0.87,1.5, height 1.45
"MH-M3-Footprint-1 - Oversized MARS2" [mil] "Oversized specific for the MARS2 Project."
  round 390 hole 150: 1(0,0)
REM30-2424SW-Footprint-1 [mil]
  round 100 hole 52: 1(-900,-300) 2(-900,-100) 3(-900,300) 4(900,400) 5(900,0) 6(900,-400)
  silkscreen extent -1000,-500 1000,500, body extent -1000,-500 1000,500, height 402
REPO-R-78E-0.5-3_V [mm] "THD, 3-Leads, Body 11.6x8.5mm, Pitch 2.54mm"
  rect 1.65x1.65 hole 1.15: 1(-2.54,0)
  round 1.65 hole 1.15: 2(0,0) 3(2.54,0)
  silkscreen extent -5.75,-2.77 5.85,6.5, body extent -5.75,-2 5.85,6.5, height 10.4
REPO-R-78XX-3_V [mm] "Module, 3-Leads, Body 11.5x7.55mm, Pitch 2.54mm"
  rect 1.75x1.75 hole 1: 1(-2.54,0)
  round 1.75 hole 1: 2(0,0) 3(2.54,0)
  silkscreen extent -5.75,-2.77 5.75,5.55, body extent -5.75,-2 5.75,5.55, height 10.2
RESC0603(1608)_L [mm] "Chip Resistor, Body 1.6x0.8mm, IPC High Density"
  rrect25% 0.66x0.76 smd: 1(-0.7,0) 2(0.7,0)
  silkscreen extent 0,-0.3 0,0.3, body extent -0.8,-0.4 0.8,0.4, height 0.45
RESC1608X55X25ML10T15 [mm] "Chip Resistor, 2-Leads, Body 1.70x0.90mm, IPC Low Density"
  rect 0.8x1 smd: 1(-0.75,0) 2(0.75,0)
  body extent -0.85,-0.45 0.85,0.45, height 0.55
RESC1609X50X30ML08T20 [mm] "Chip Resistor, 2-Leads, Body 1.65x0.95mm, IPC Low Density"
  rect 0.9x1.05 smd: 1(-0.7,0) 2(0.7,0)
  body extent -0.82,-0.48 0.82,0.48, height 0.5
RESC3216X70X50NL05T20 [mm] "Chip Resistor, 2-Leads, Body 3.20x1.60mm, IPC Medium Density"
  rect 1.1x1.65 smd: 1(-1.425,0) 2(1.425,0)
  silkscreen extent -0.5,-0.72 0.5,0.72, body extent -1.63,-0.82 1.62,0.82, height 0.7
ROHM-SOT723-3_V [mm] "SOT723, 3-Leads, Body 1.2x0.8mm, Pitch 0.8mm"
  rrect30% 0.45x0.4 smd: 1(-0.575,0.4) 2(-0.575,-0.4)
  rrect30% 0.45x0.5 smd: 3(0.575,0)
  body extent -0.53,-0.63 0.53,0.63, height 0.45
SMTC-ESQ-132-14-X-D [mm] "Elevated Socket, 2x32 Pins, Vertical, 2.54mm Pitch, Female"
  rect 1.55x1.55 hole 1.02: 1(0,0)
  round 1.55 hole 1.02: 2(0,-2.54) 3(2.54,0) 4(2.54,-2.54) 5(5.08,0) 6(5.08,-2.54) 7(7.62,0) 8(7.62,-2.54) 9(10.16,0) 10(10.16,-2.54) 11(12.7,0) 12(12.7,-2.54) 13(15.24,0) 14(15.24,-2.54) 15(17.78,0) 16(17.78,-2.54) 17(20.32,0) 18(20.32,-2.54) 19(22.86,0) 20(22.86,-2.54) 21(25.4,0) 22(25.4,-2.54) 23(27.94,0) 24(27.94,-2.54) 25(30.48,0) 26(30.48,-2.54) 27(33.02,0) 28(33.02,-2.54) 29(35.56,0) 30(35.56,-2.54) 31(38.1,0) 32(38.1,-2.54) 33(40.64,0) 34(40.64,-2.54) 35(43.18,0) 36(43.18,-2.54) 37(45.72,0) 38(45.72,-2.54) 39(48.26,0) 40(48.26,-2.54) 41(50.8,0) 42(50.8,-2.54) 43(53.34,0) 44(53.34,-2.54) 45(55.88,0) 46(55.88,-2.54) 47(58.42,0) 48(58.42,-2.54) 49(60.96,0) 50(60.96,-2.54) 51(63.5,0) 52(63.5,-2.54) 53(66.04,0) 54(66.04,-2.54) 55(68.58,0) 56(68.58,-2.54) 57(71.12,0) 58(71.12,-2.54) 59(73.66,0) 60(73.66,-2.54) 61(76.2,0) 62(76.2,-2.54) 63(78.74,0) 64(78.74,-2.54)
  silkscreen extent -1.53,-3.74 80.27,1.2, body extent -1.52,-3.81 80.26,1.27, height 11.05
SOT95P280X145-5M [mm] "SOT23, 5-Leads, Body 2.90x2.80mm, Pitch 0.95mm, IPC Low Density"
  rect 1.2x0.65 smd: 1(-1.475,0.95) 2(-1.475,0) 3(-1.475,-0.95) 4(1.475,-0.95) 5(1.475,0.95)
  silkscreen extent -1.6,-1.55 0.5,1.95, body extent -1.5,-1.53 1.5,1.53, height 1.45
SOT95P280X145-6M [mm] "SOT23, 6-Leads, Body 2.90x2.80mm, Pitch 0.95mm, IPC Low Density"
  rect 1.2x0.65 smd: 1(-1.475,0.95) 2(-1.475,0) 3(-1.475,-0.95) 4(1.475,-0.95) 5(1.475,0) 6(1.475,0.95)
  silkscreen extent -1.6,-1.55 0.5,1.95, body extent -1.5,-1.53 1.5,1.53, height 1.45
TestPoint-5005-Footprint-1 [mil]
  round 103 hole 63: 1(0,0)
  silkscreen extent -72,-72 72,72, body extent -63,-61 62,64, height 215
TO228P970-3N [mm]
  rect 3.3x1.25 smd: 1(-4.5,2.28) 3(-4.5,-2.28)
  rect 7.5x5.6 smd: 2(2,0)
  silkscreen extent -4.62,-3.3 -2.15,3.58, body extent -4.2,-3.3 5.53,3.3, height 2.63
V375C24C150BL-Footprint-1 [mil]
  oval 150x200 hole 94: 1(400,1000) 4(-400,1000) 5(-400,-1000) 7(400,-1000)
  round 150 hole 94: 2(125,1000) 3(-125,1000) 6(0,-1000)
  round 250 hole 128.5: MT1(-635,650) MT2(-635,0) MT3(-635,-650) MT4(635,-650) MT5(635,0) MT6(635,650)
  silkscreen extent -725,-1140 725,1140, body extent -725,-1135 725,1145, height 530
"WE-LQS 8040" [mm] "SMD Power Inductor, 2-Leads, Body 8.0x8.0mm"
  rect 2.2x7.5 smd: 1(-3,0) 2(3,0)
  body extent -4,-4 4,4, height 4.16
